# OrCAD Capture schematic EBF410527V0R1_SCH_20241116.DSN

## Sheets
1 01  Content: title: 野火_LubanCat_RV06_IOS_底板原理图; rev: V0R2; note: Content; note: https://yehuosm.tmall.com
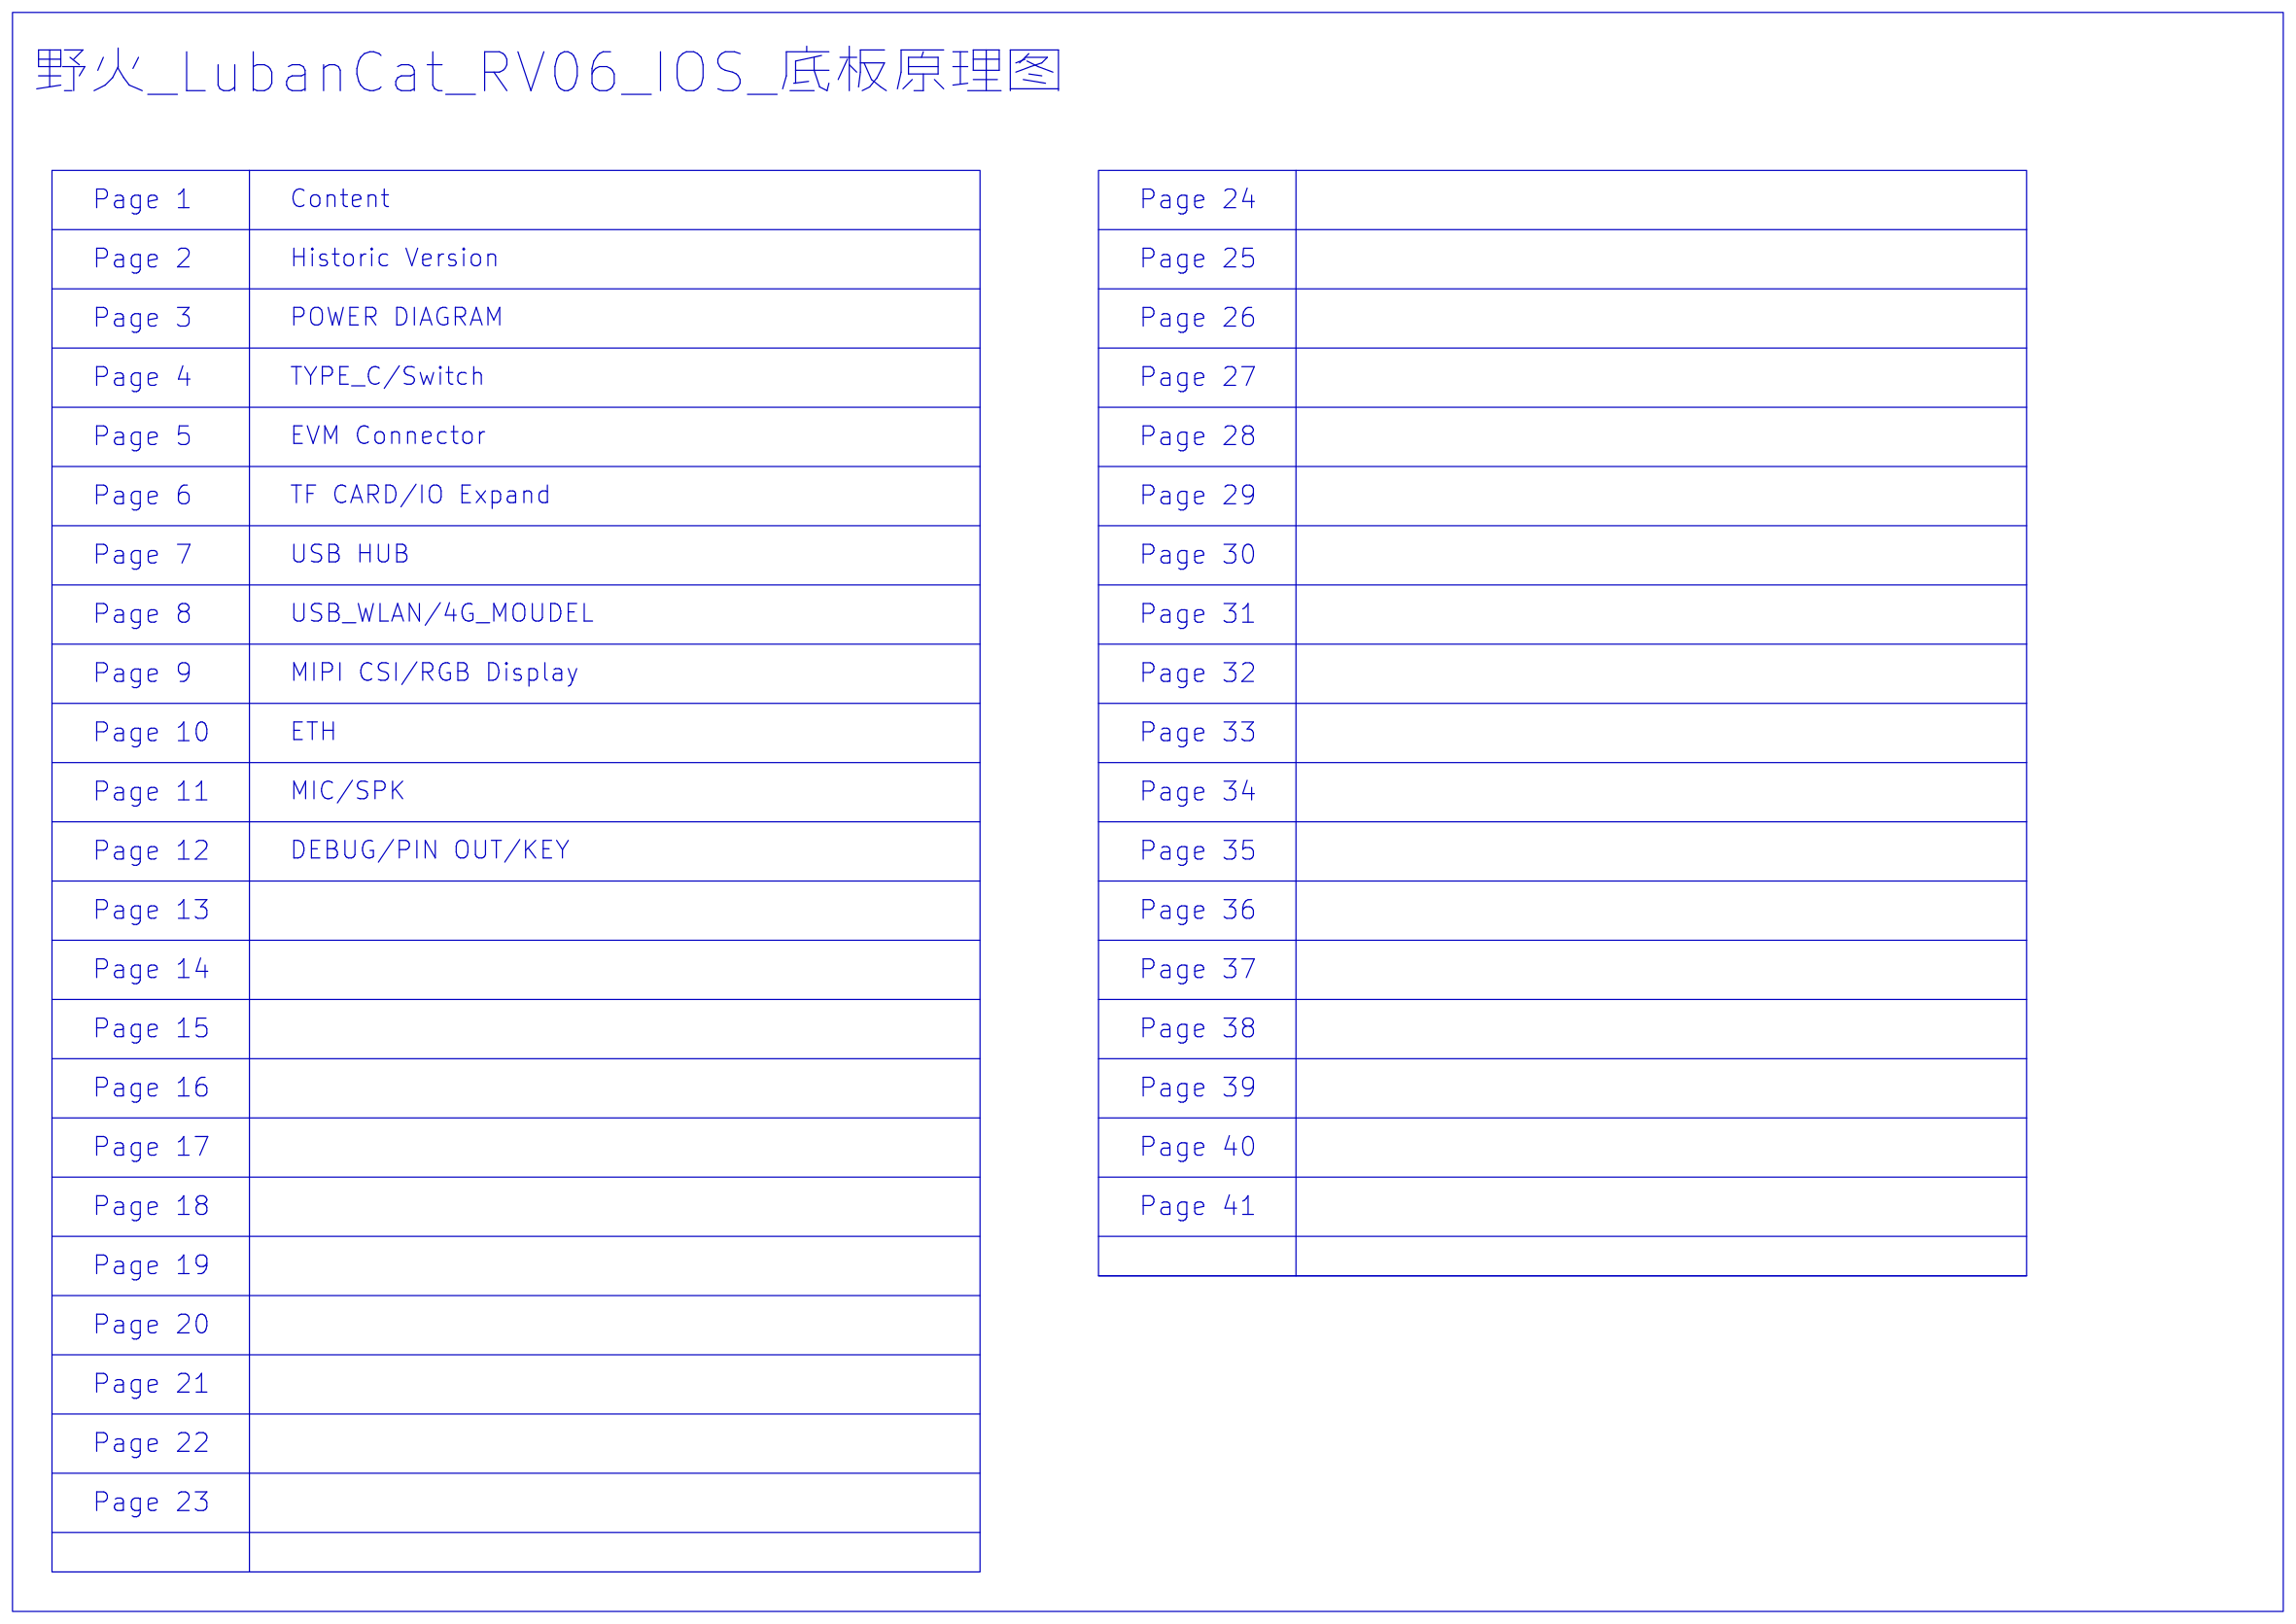
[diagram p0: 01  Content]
2 02 Historic Version: note: Historic Version
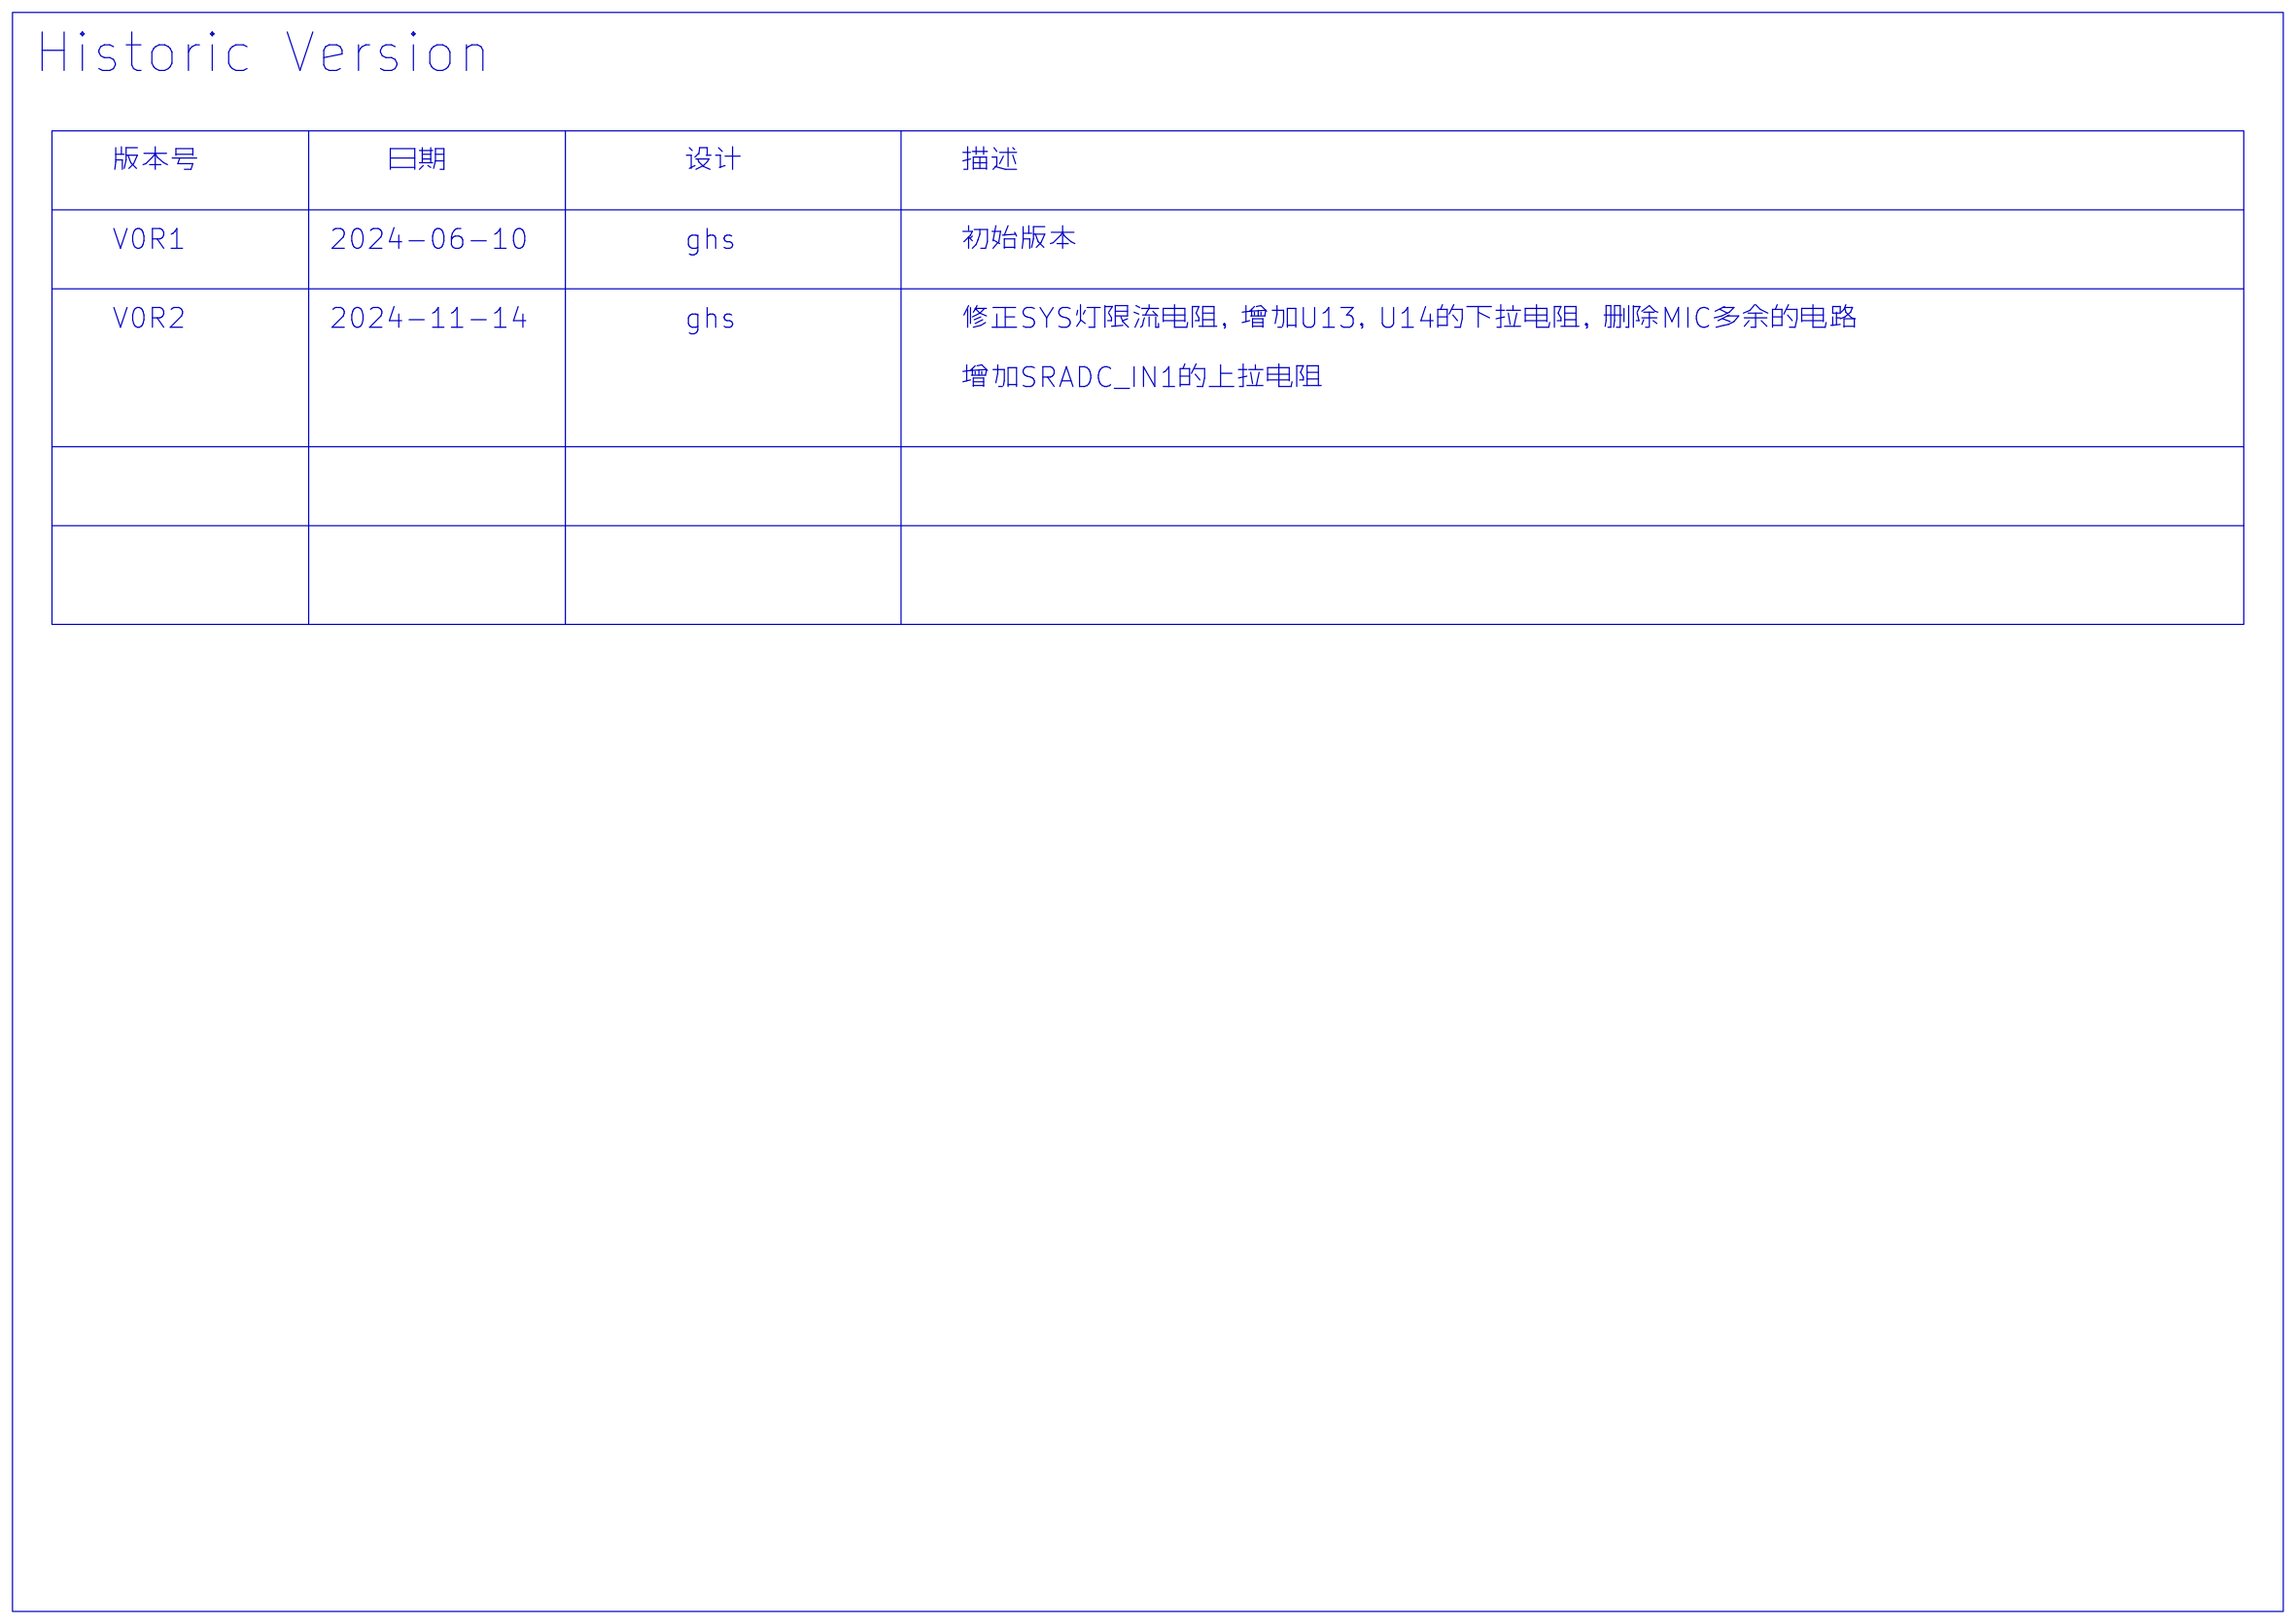
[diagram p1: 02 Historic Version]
3 03 POWER DIAGRAM: note: POWER DIAGRAM
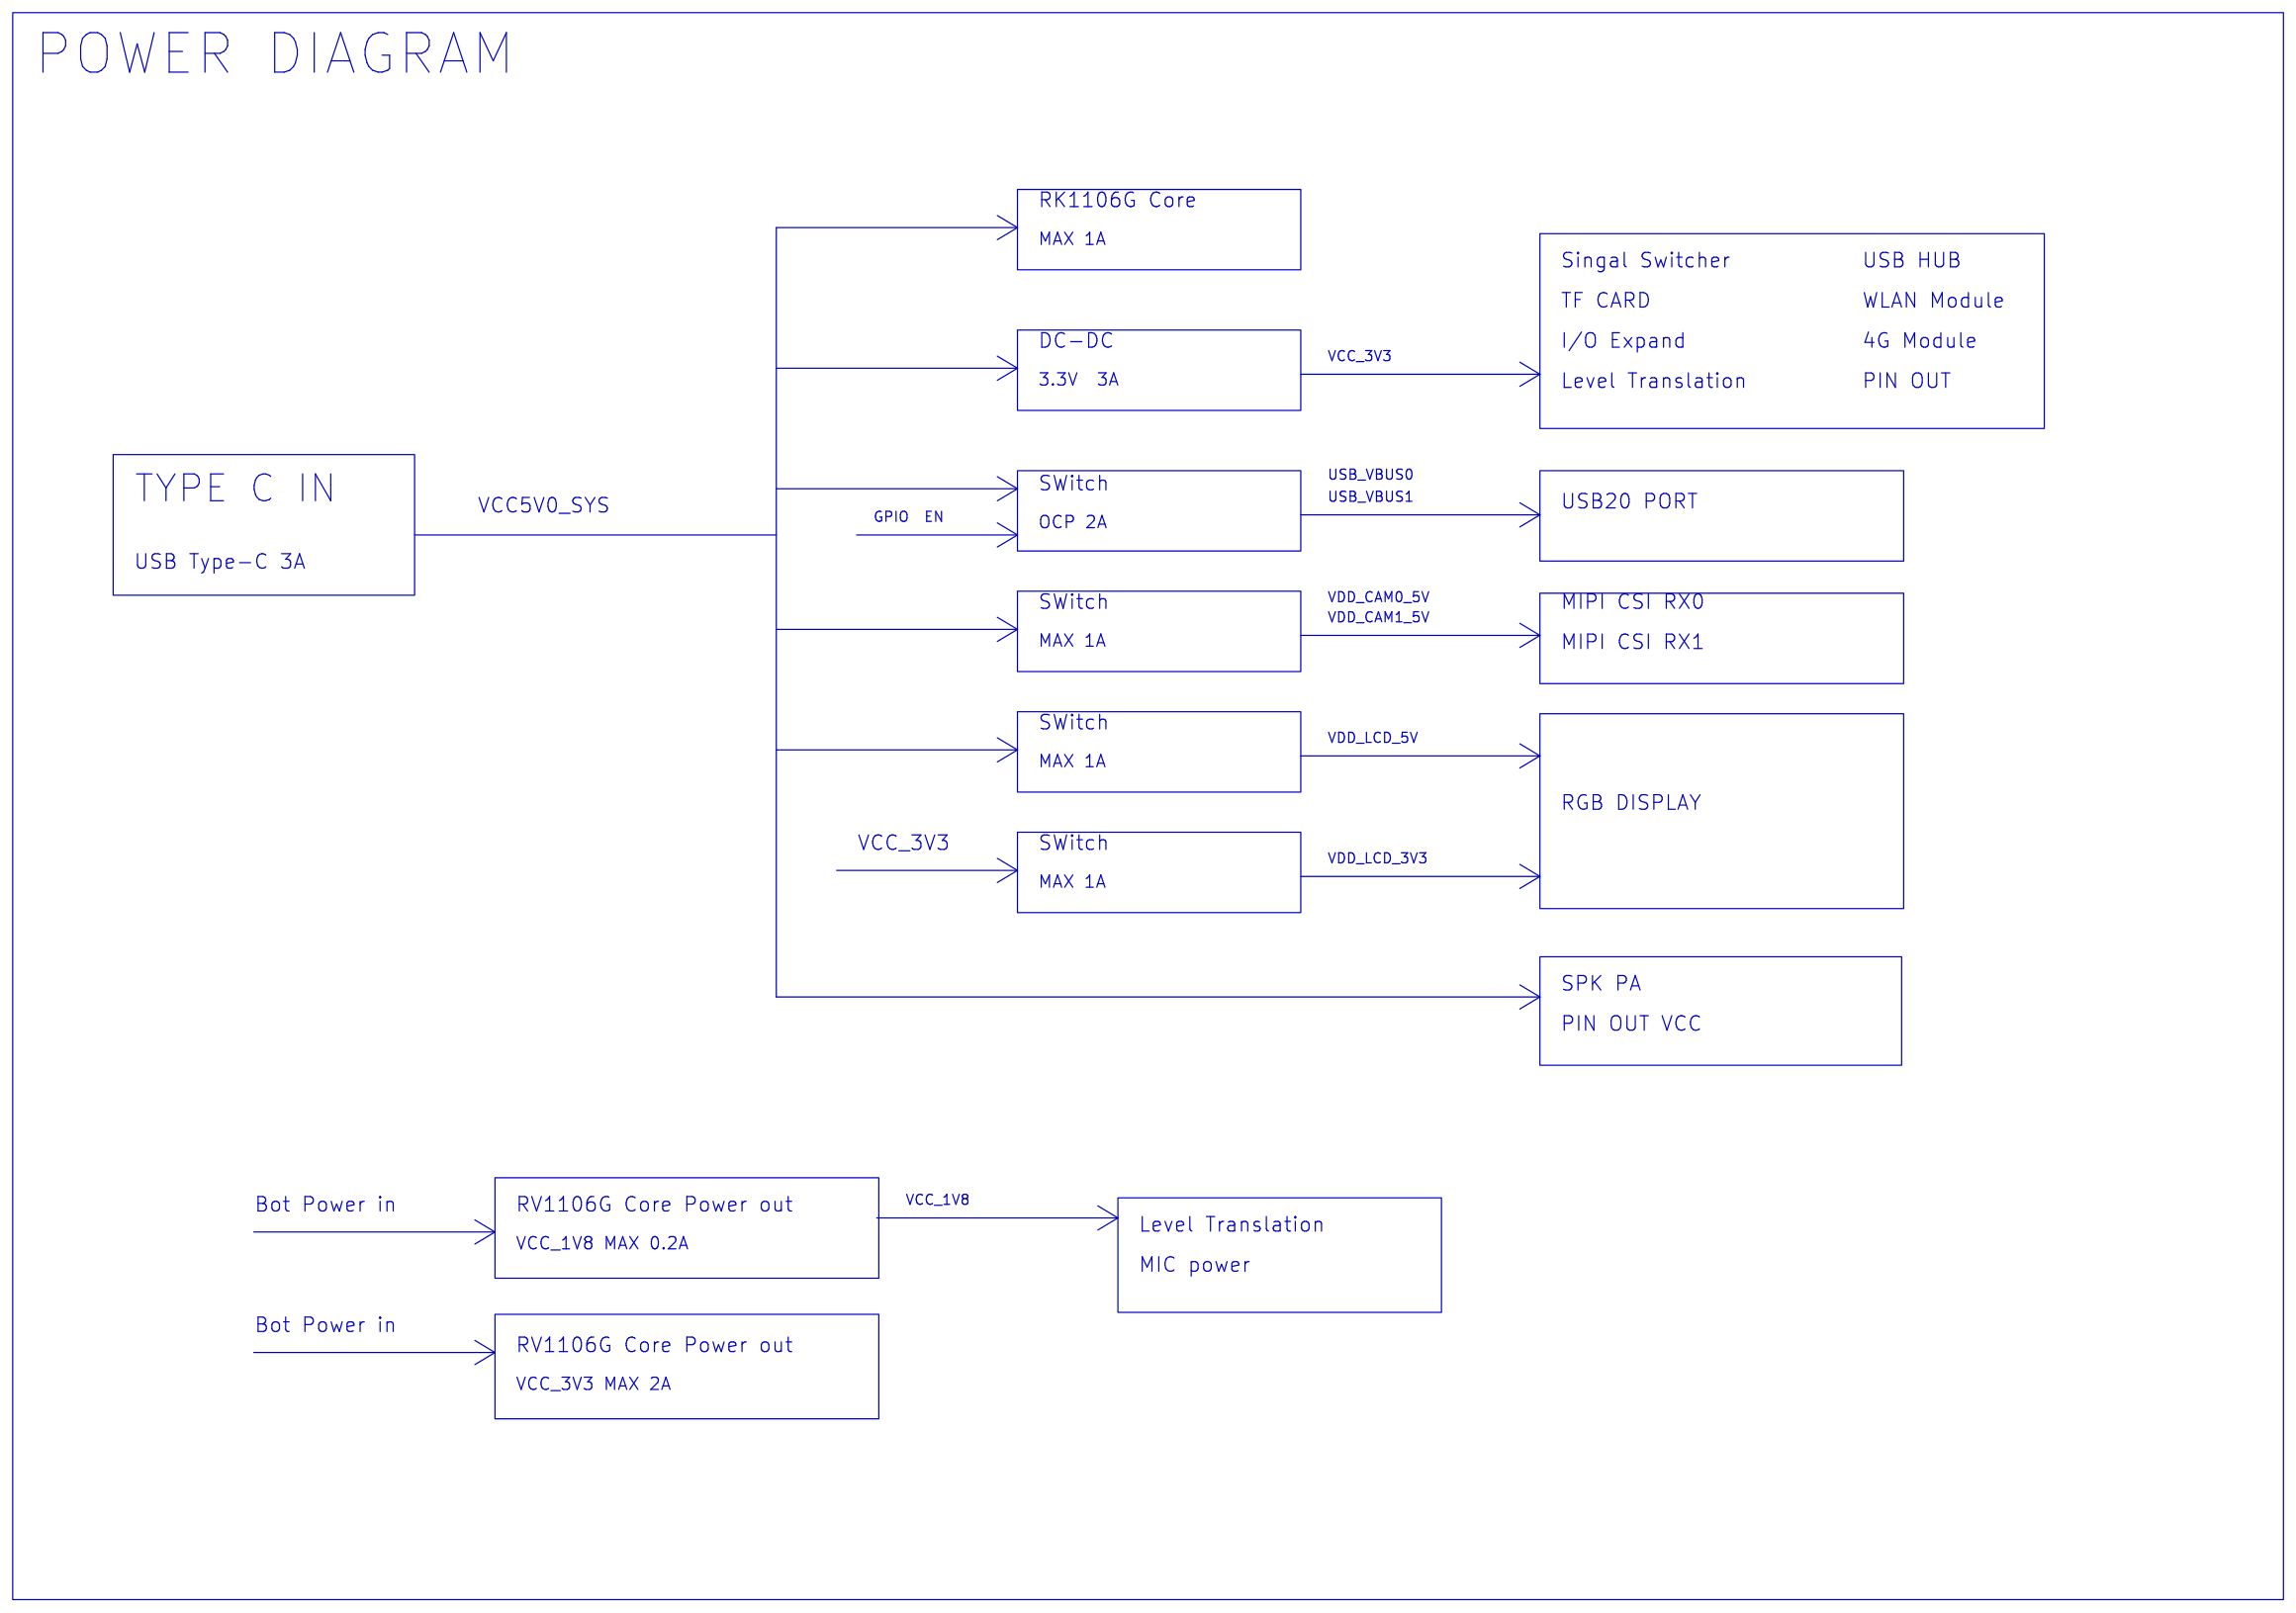
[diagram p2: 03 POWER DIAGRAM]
4 05 EVM Connector: size A3; note: EVM Connector
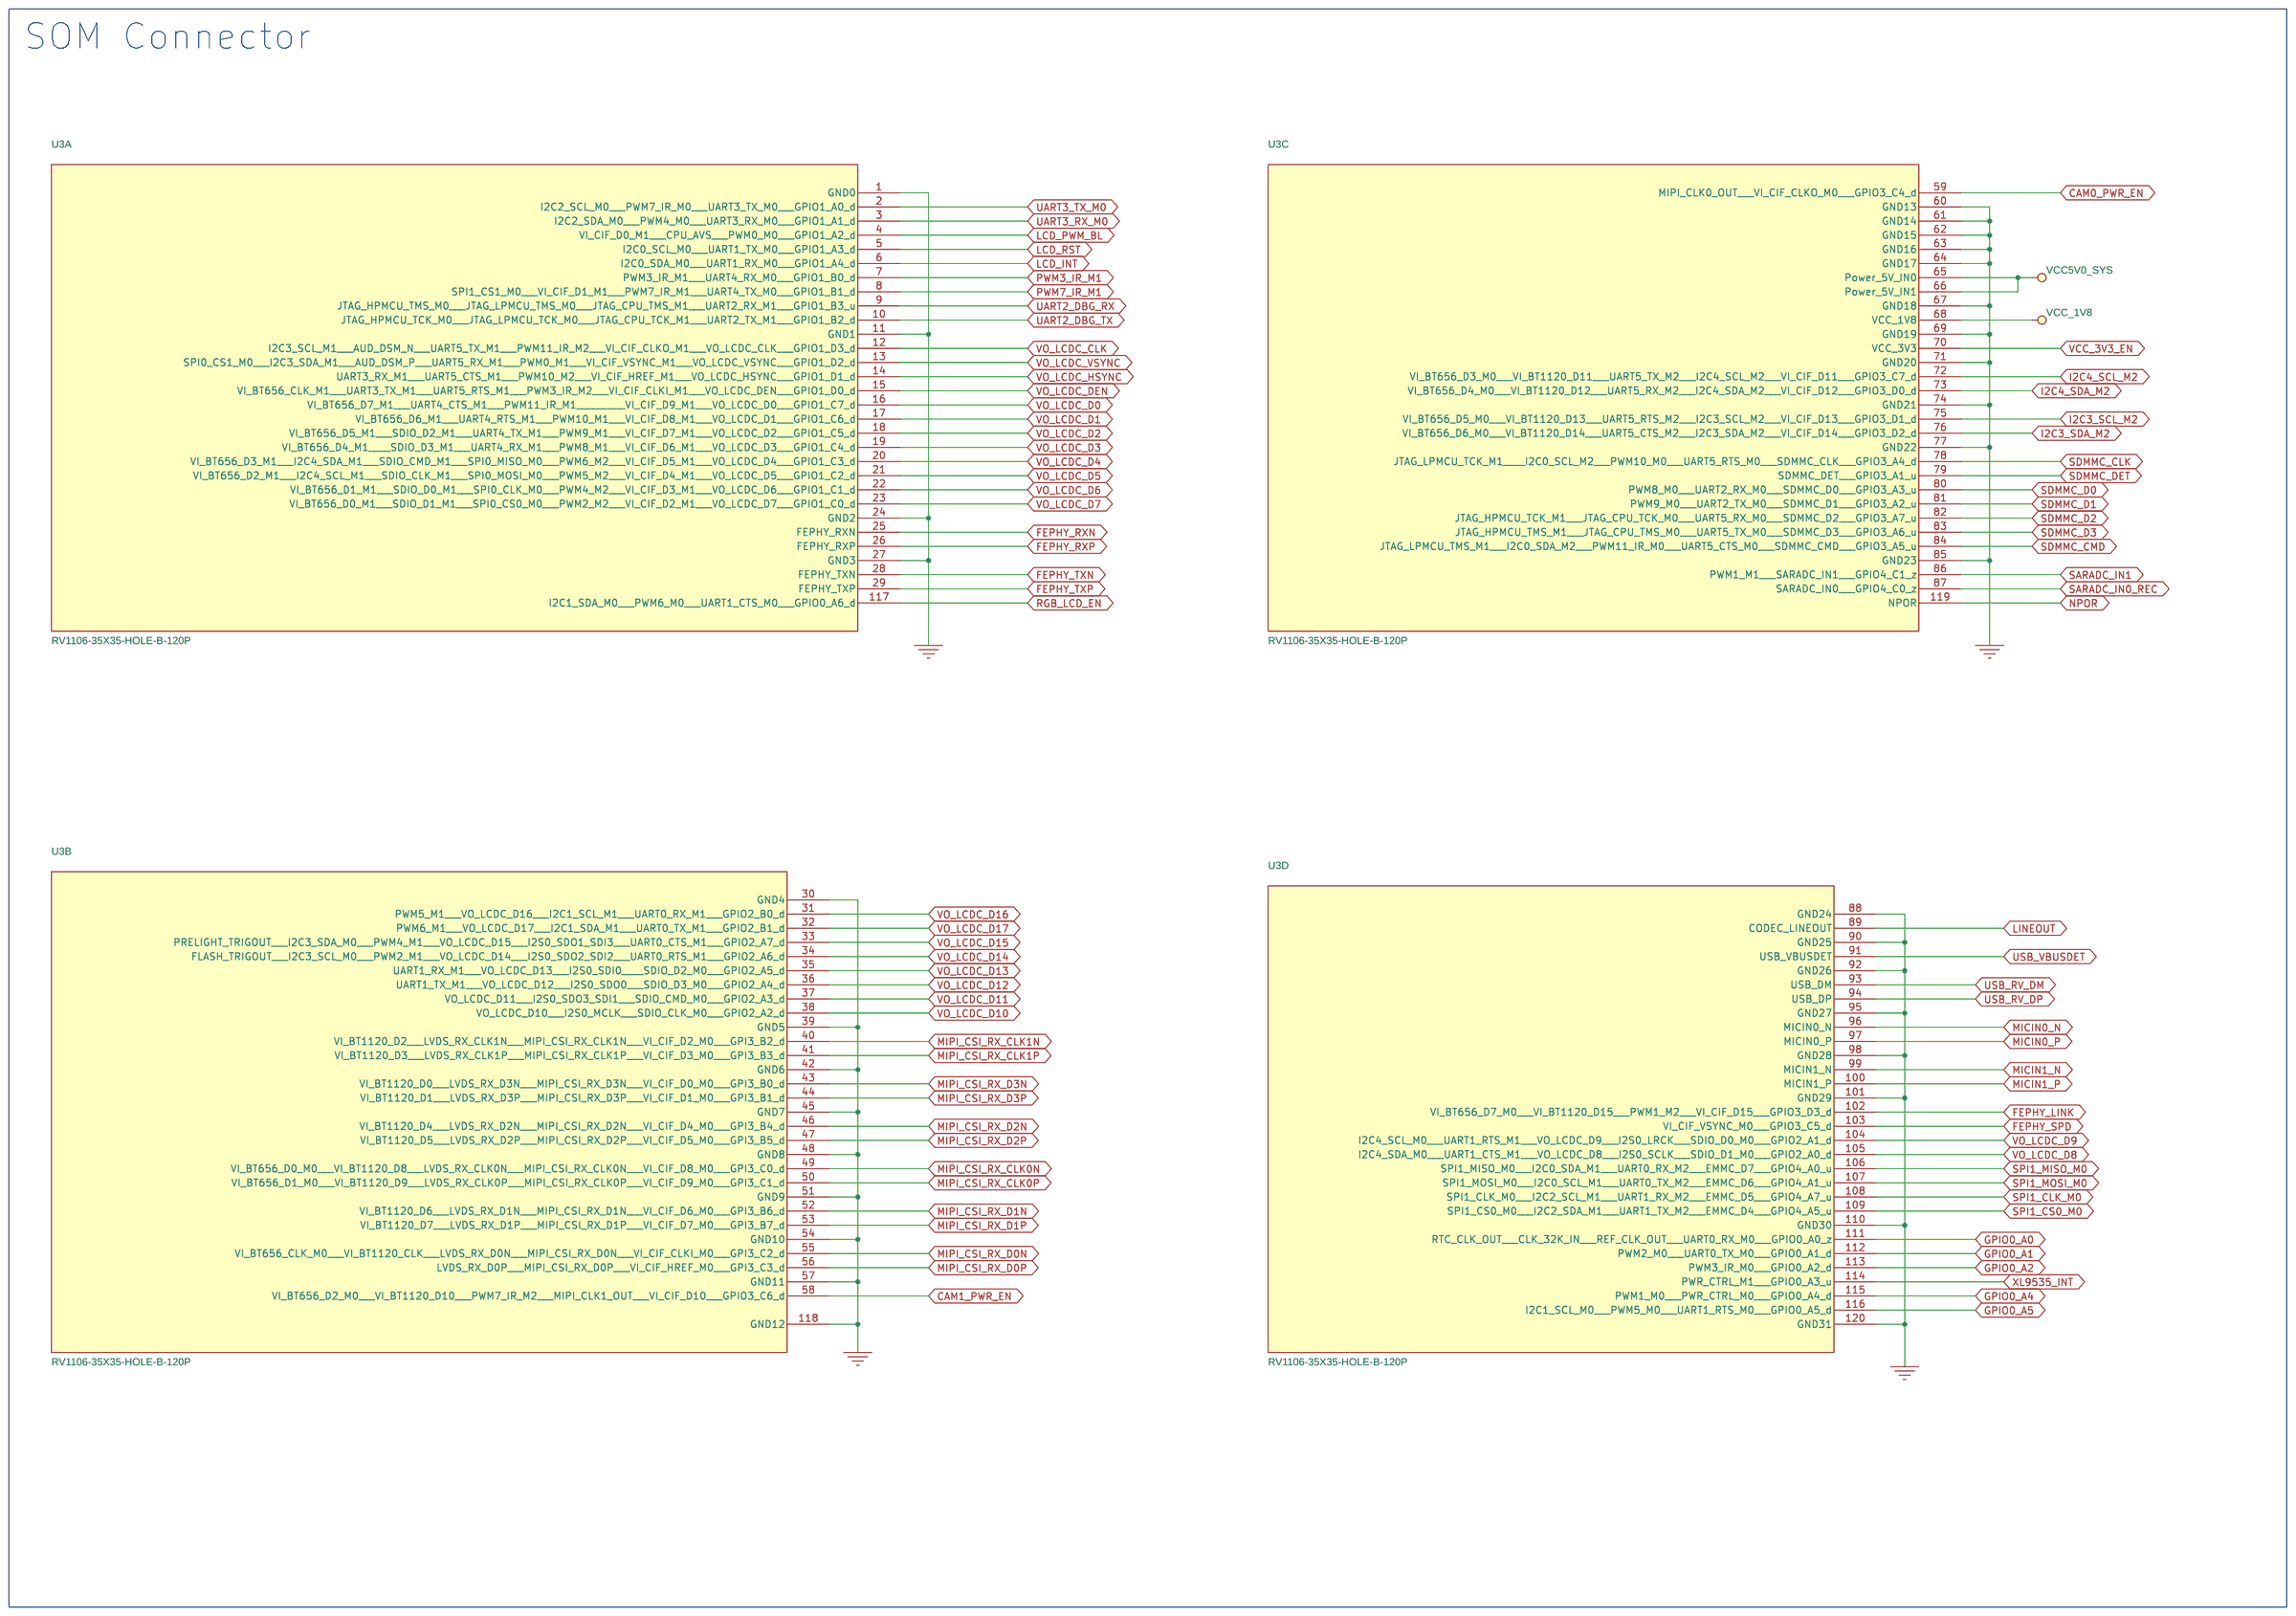
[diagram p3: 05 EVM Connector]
5 07 USB HUB: size A4; note: USB HUB
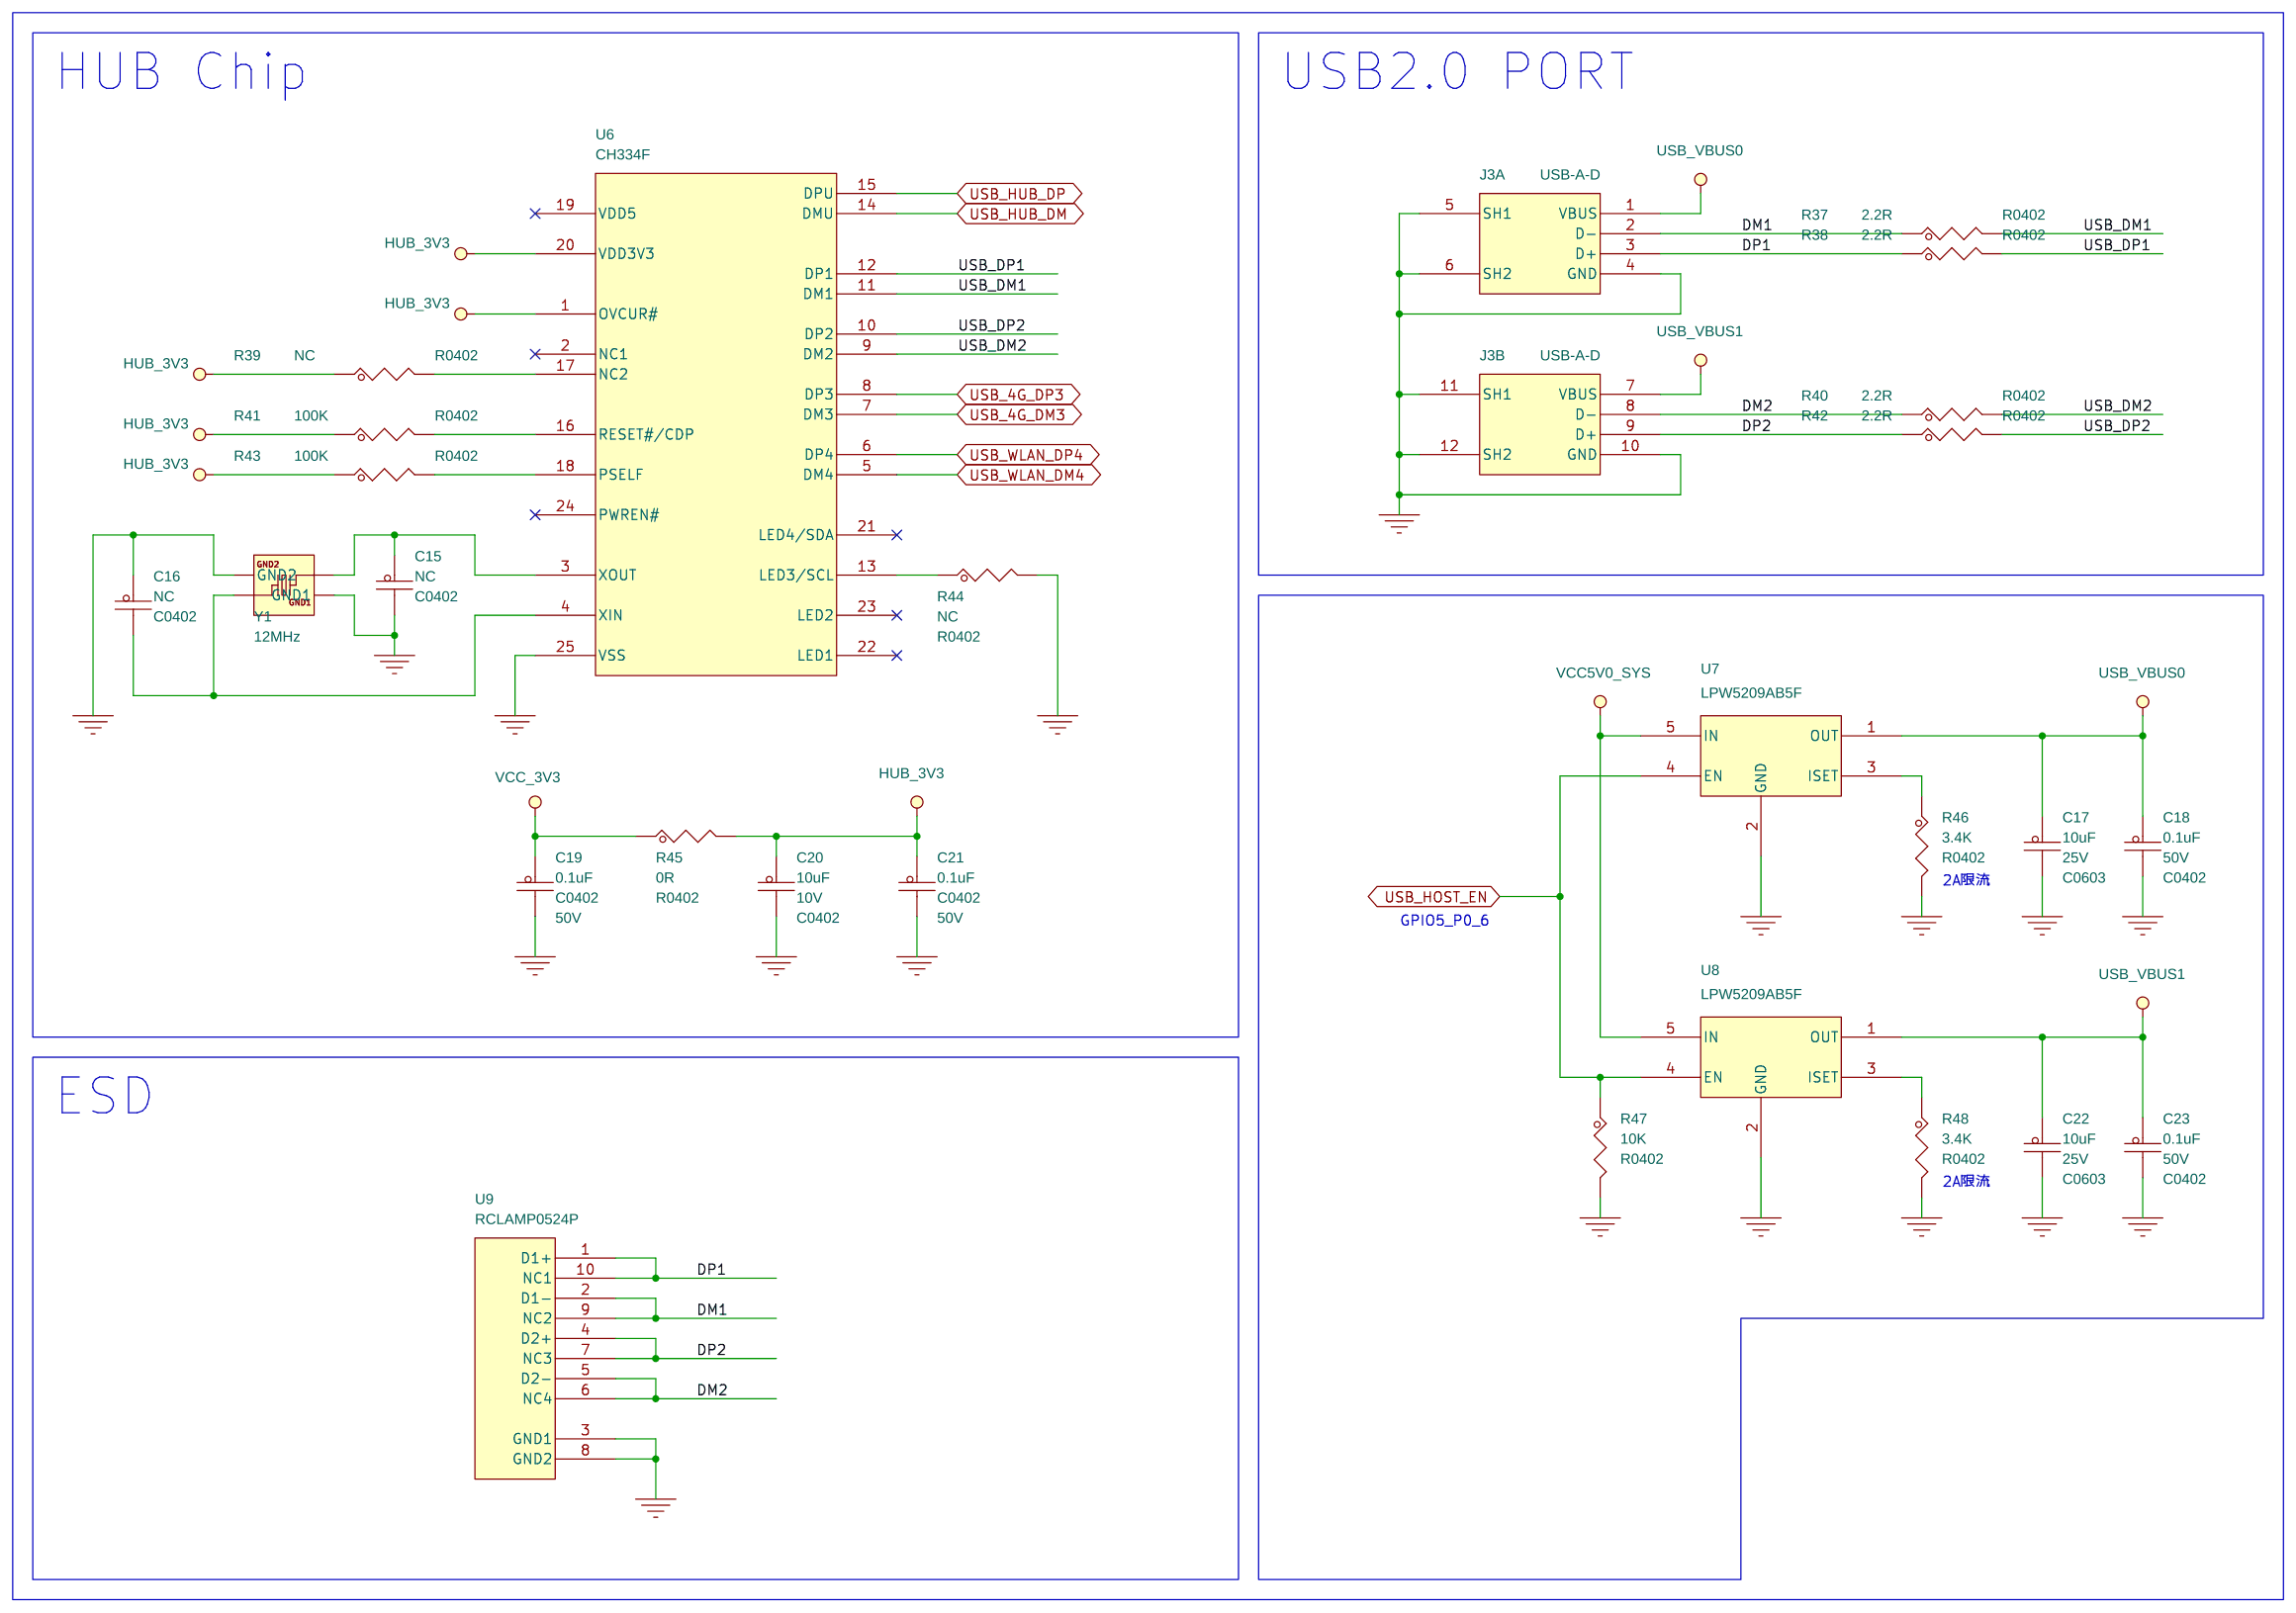
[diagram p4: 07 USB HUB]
6 10 ETH: size A4; note: ETH
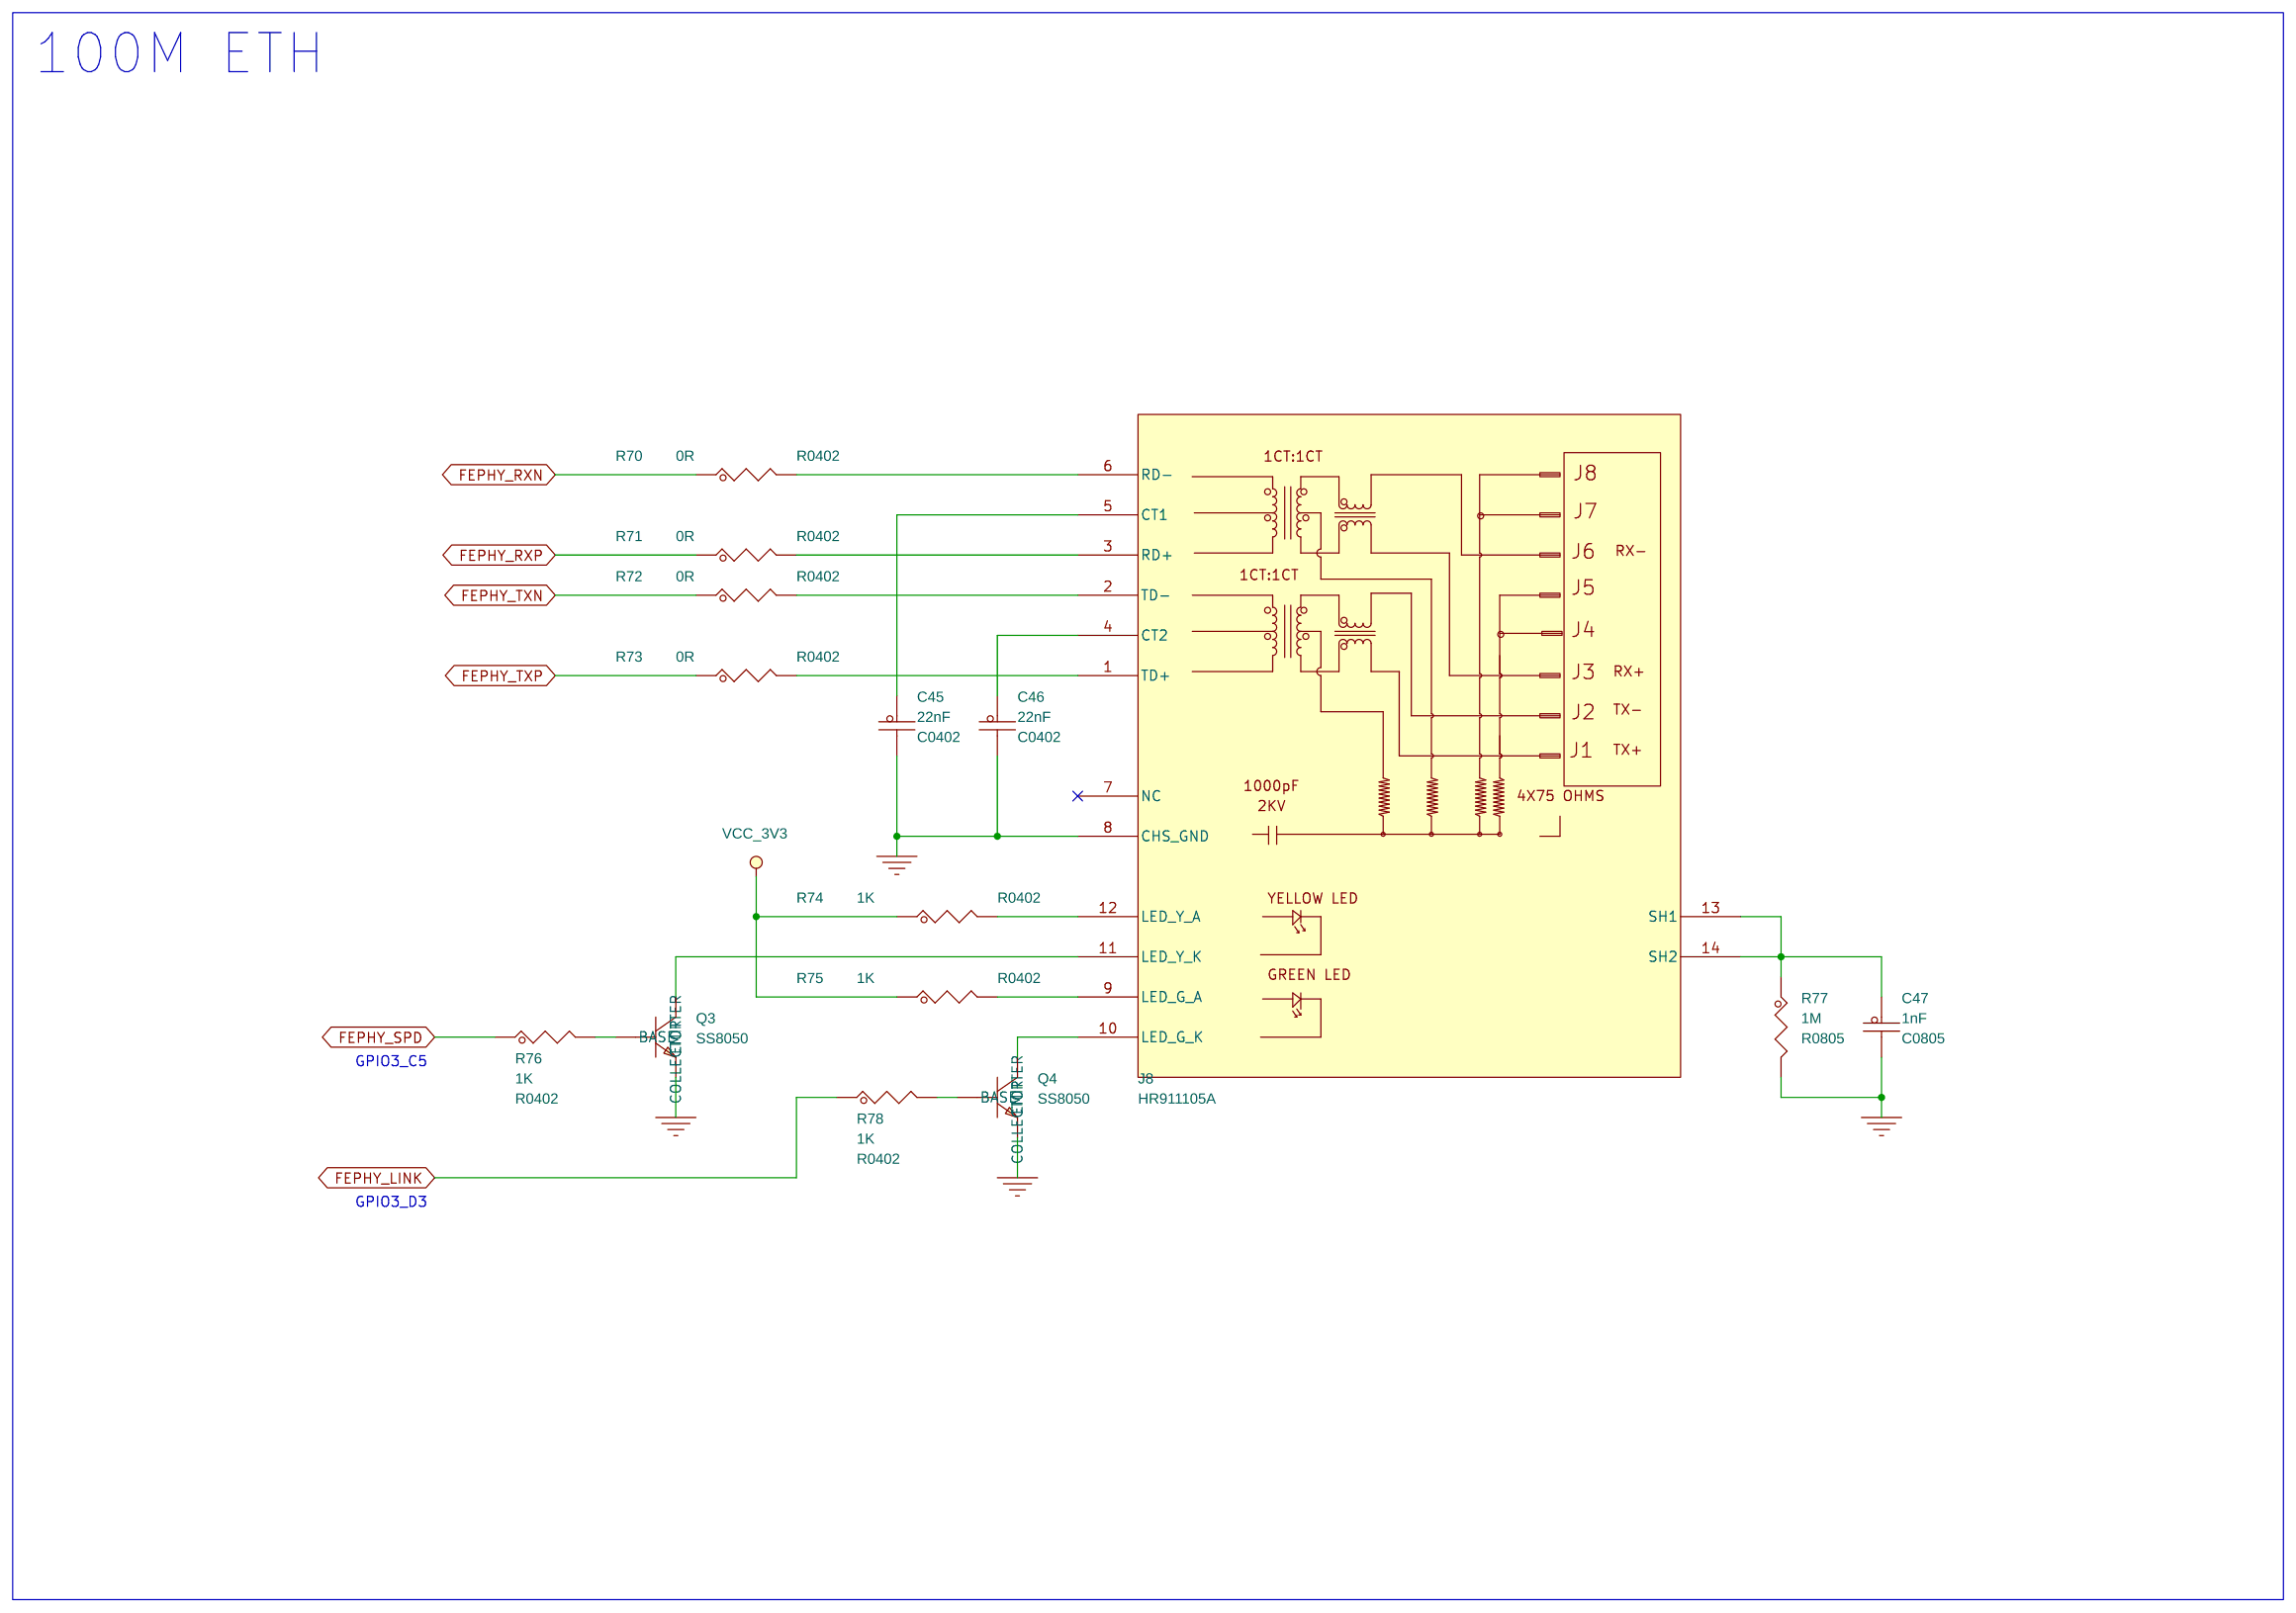
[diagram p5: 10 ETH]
7 11 MIC/SPK: size A4; note: MIC/SPK
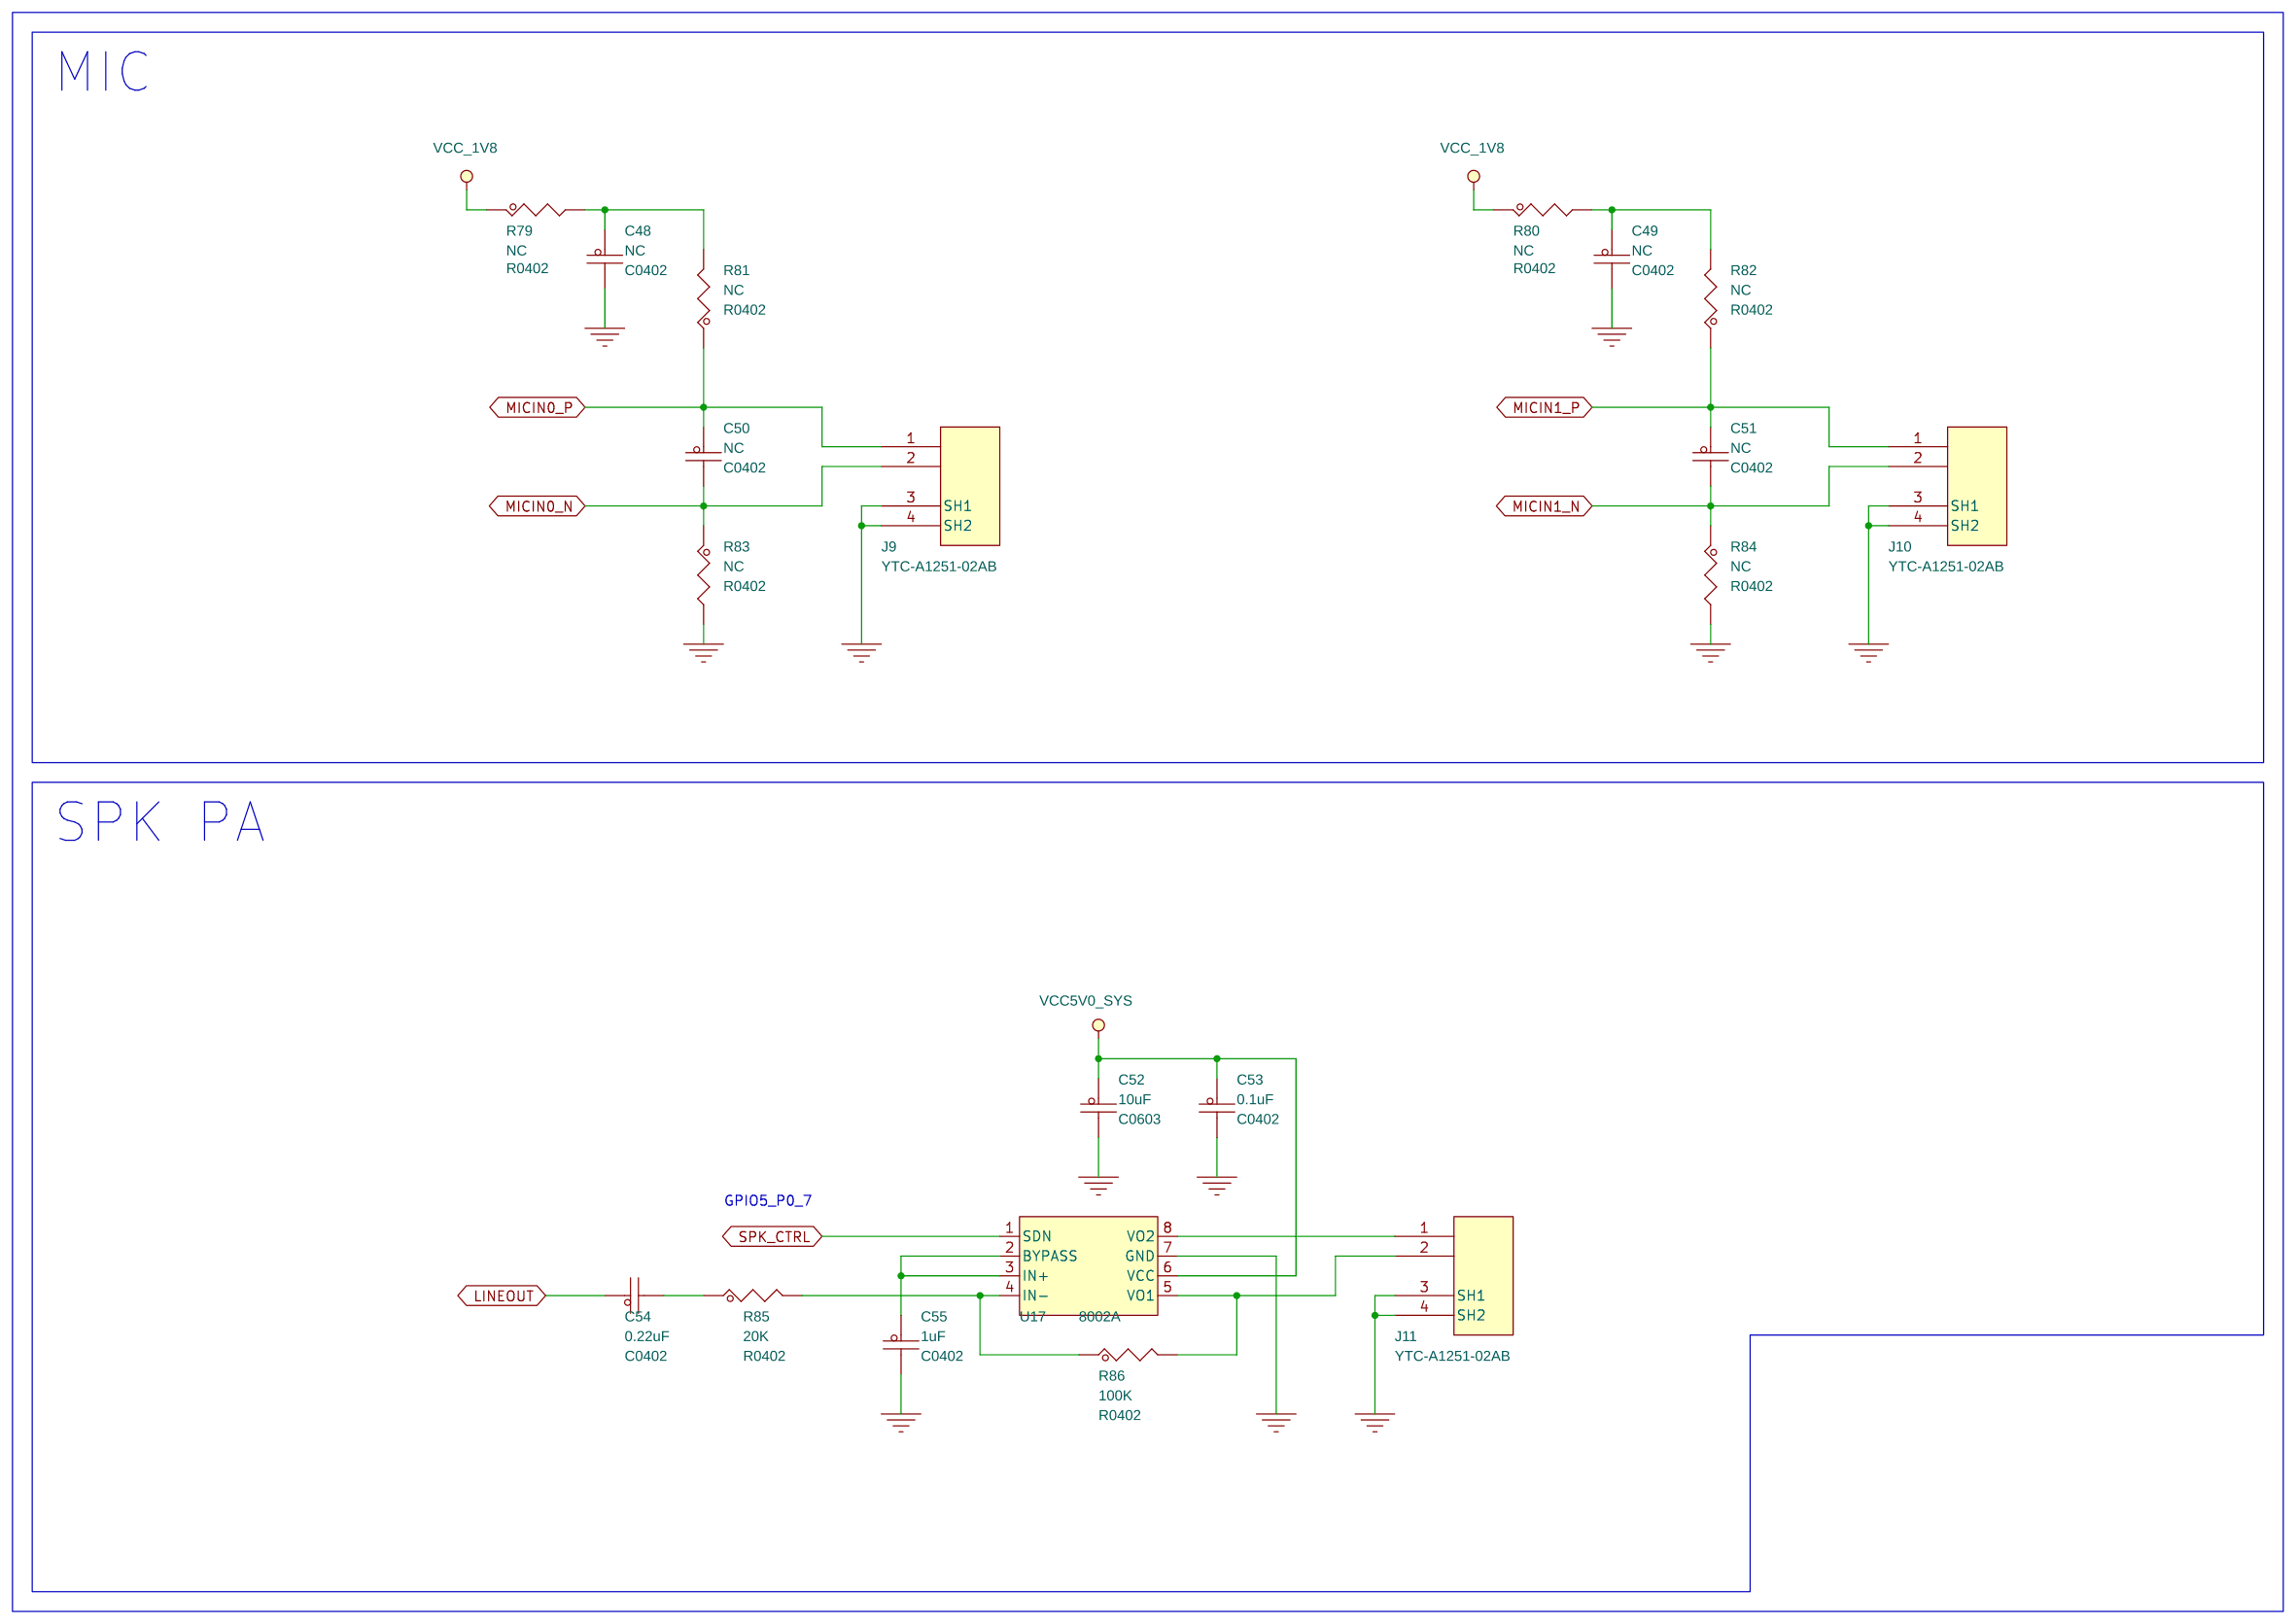
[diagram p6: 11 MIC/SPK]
8 04 TYPE_C/Switch: size A4; note: TYPE_C/Switch
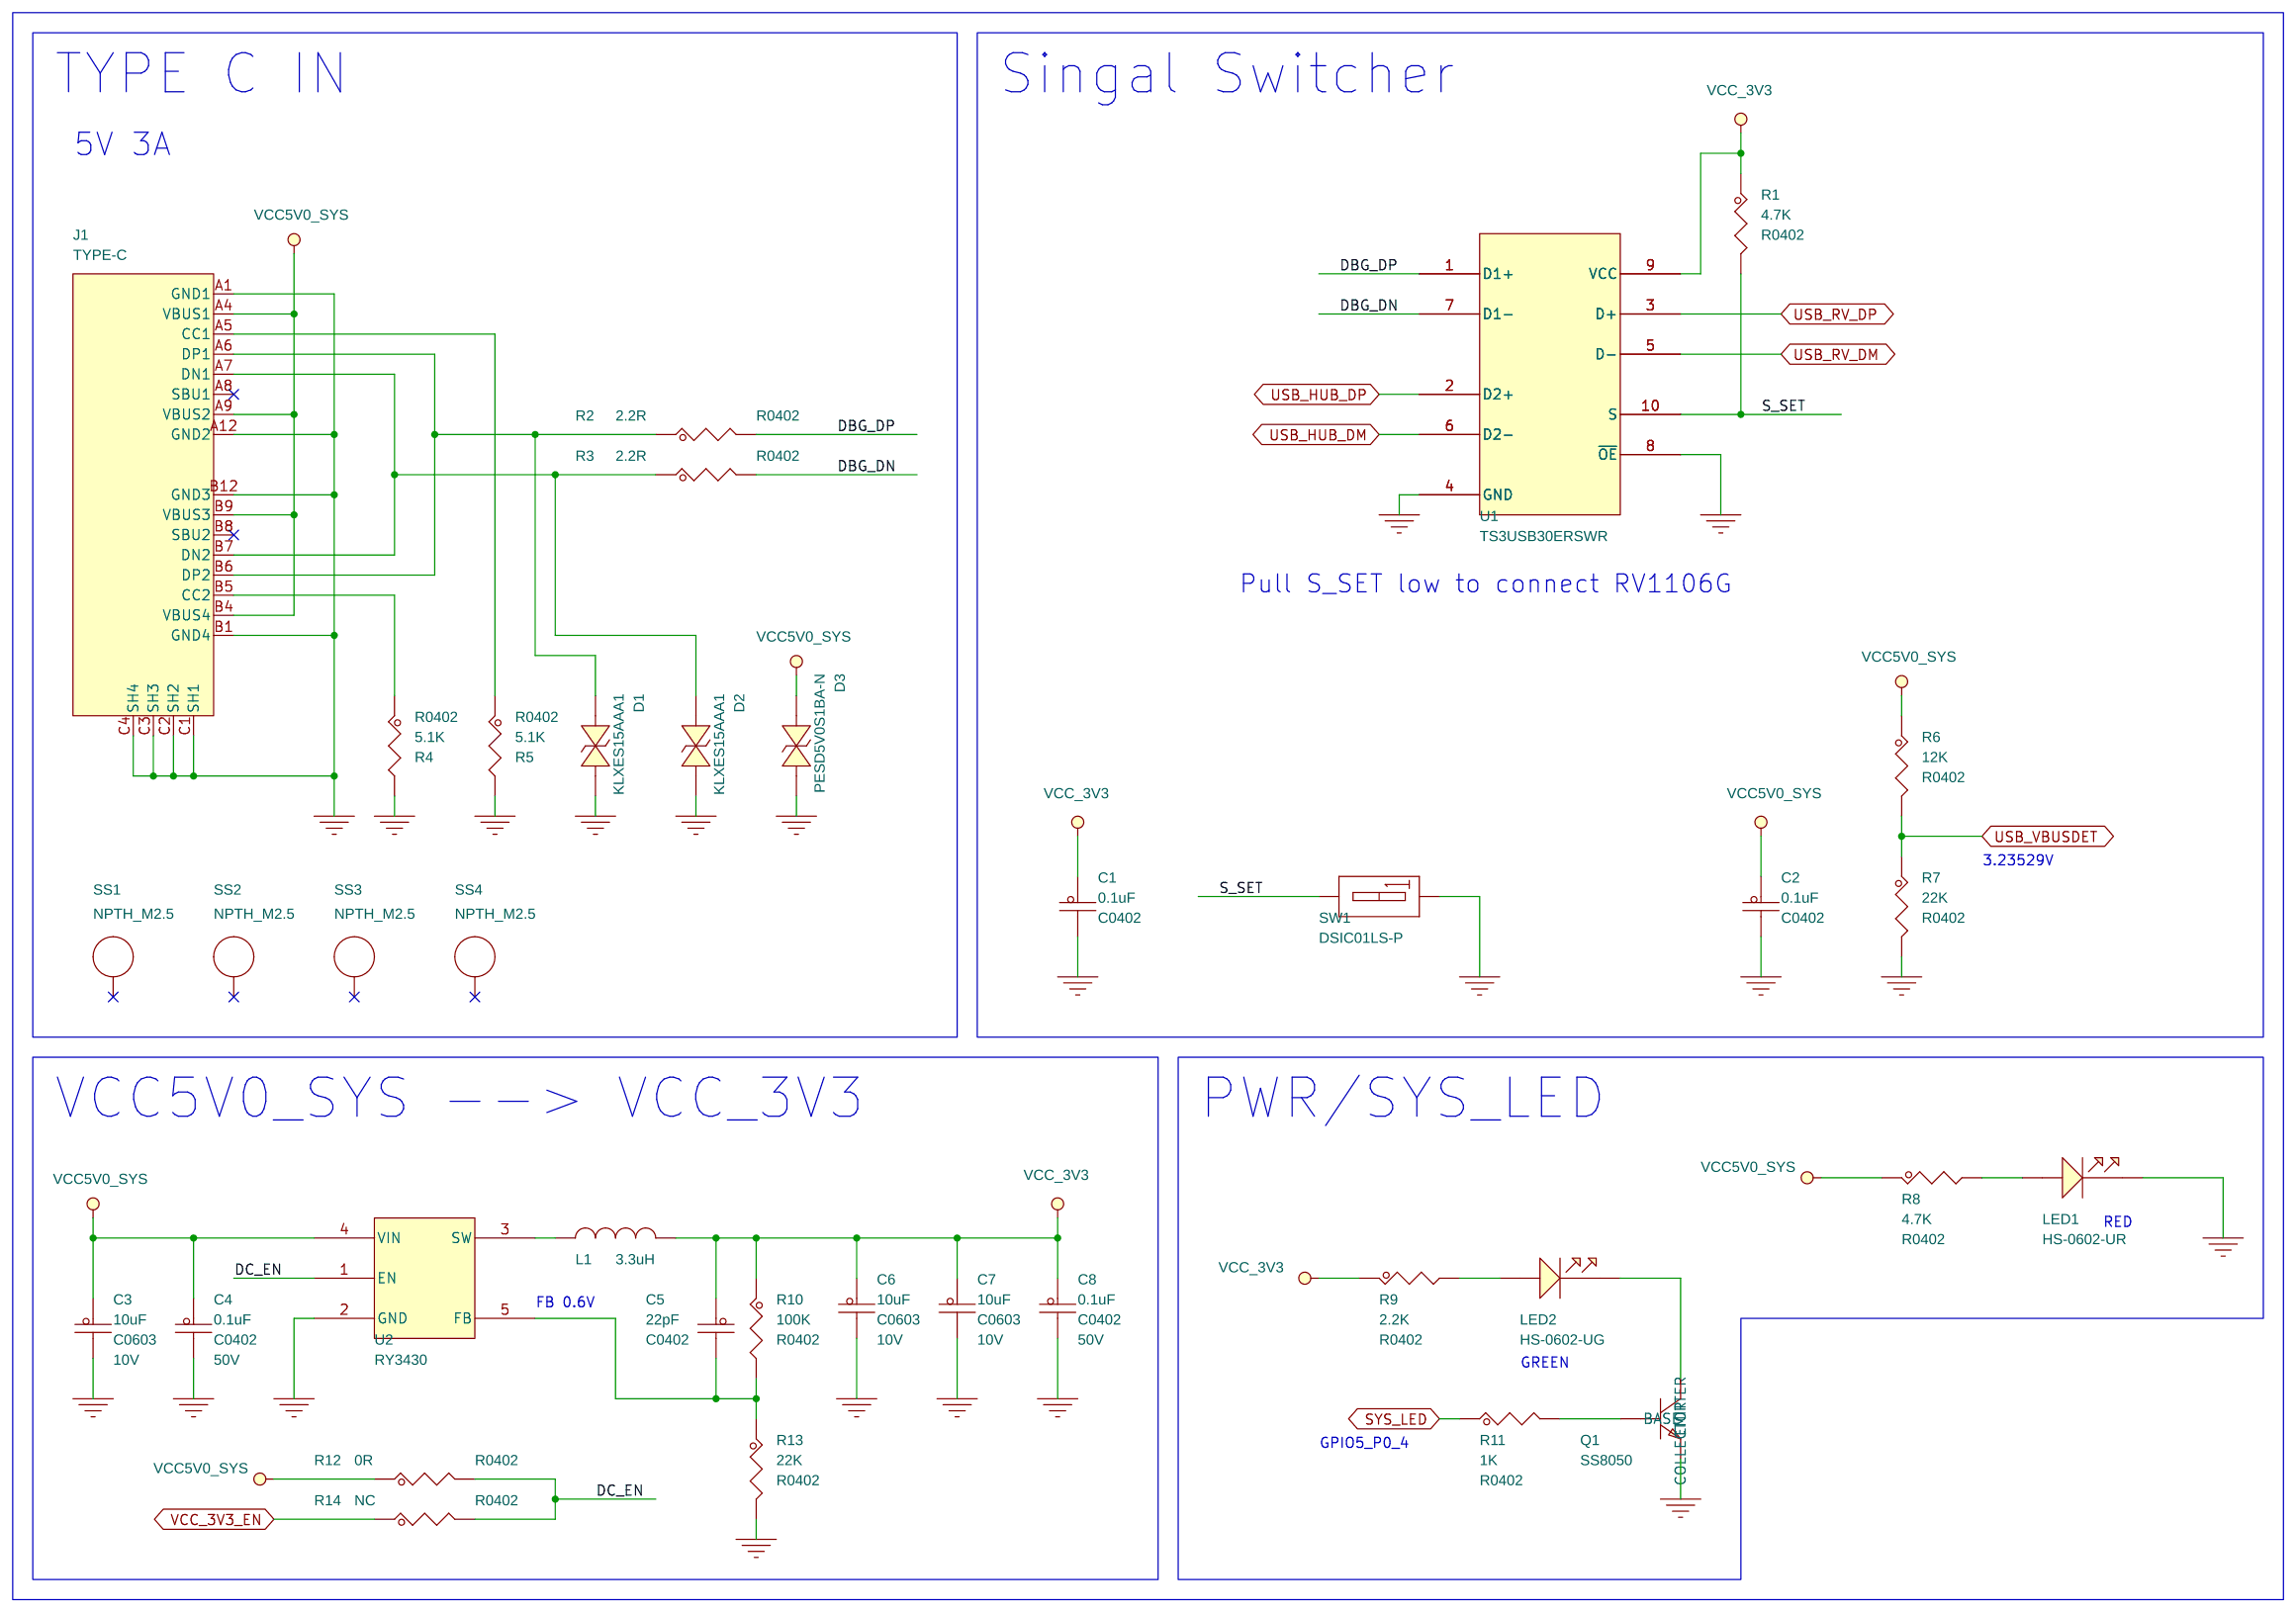
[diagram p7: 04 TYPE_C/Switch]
9 12 DEBUG/PIN OUT/KEY: size A4; note: DEBUG/PIN OUT/KEY
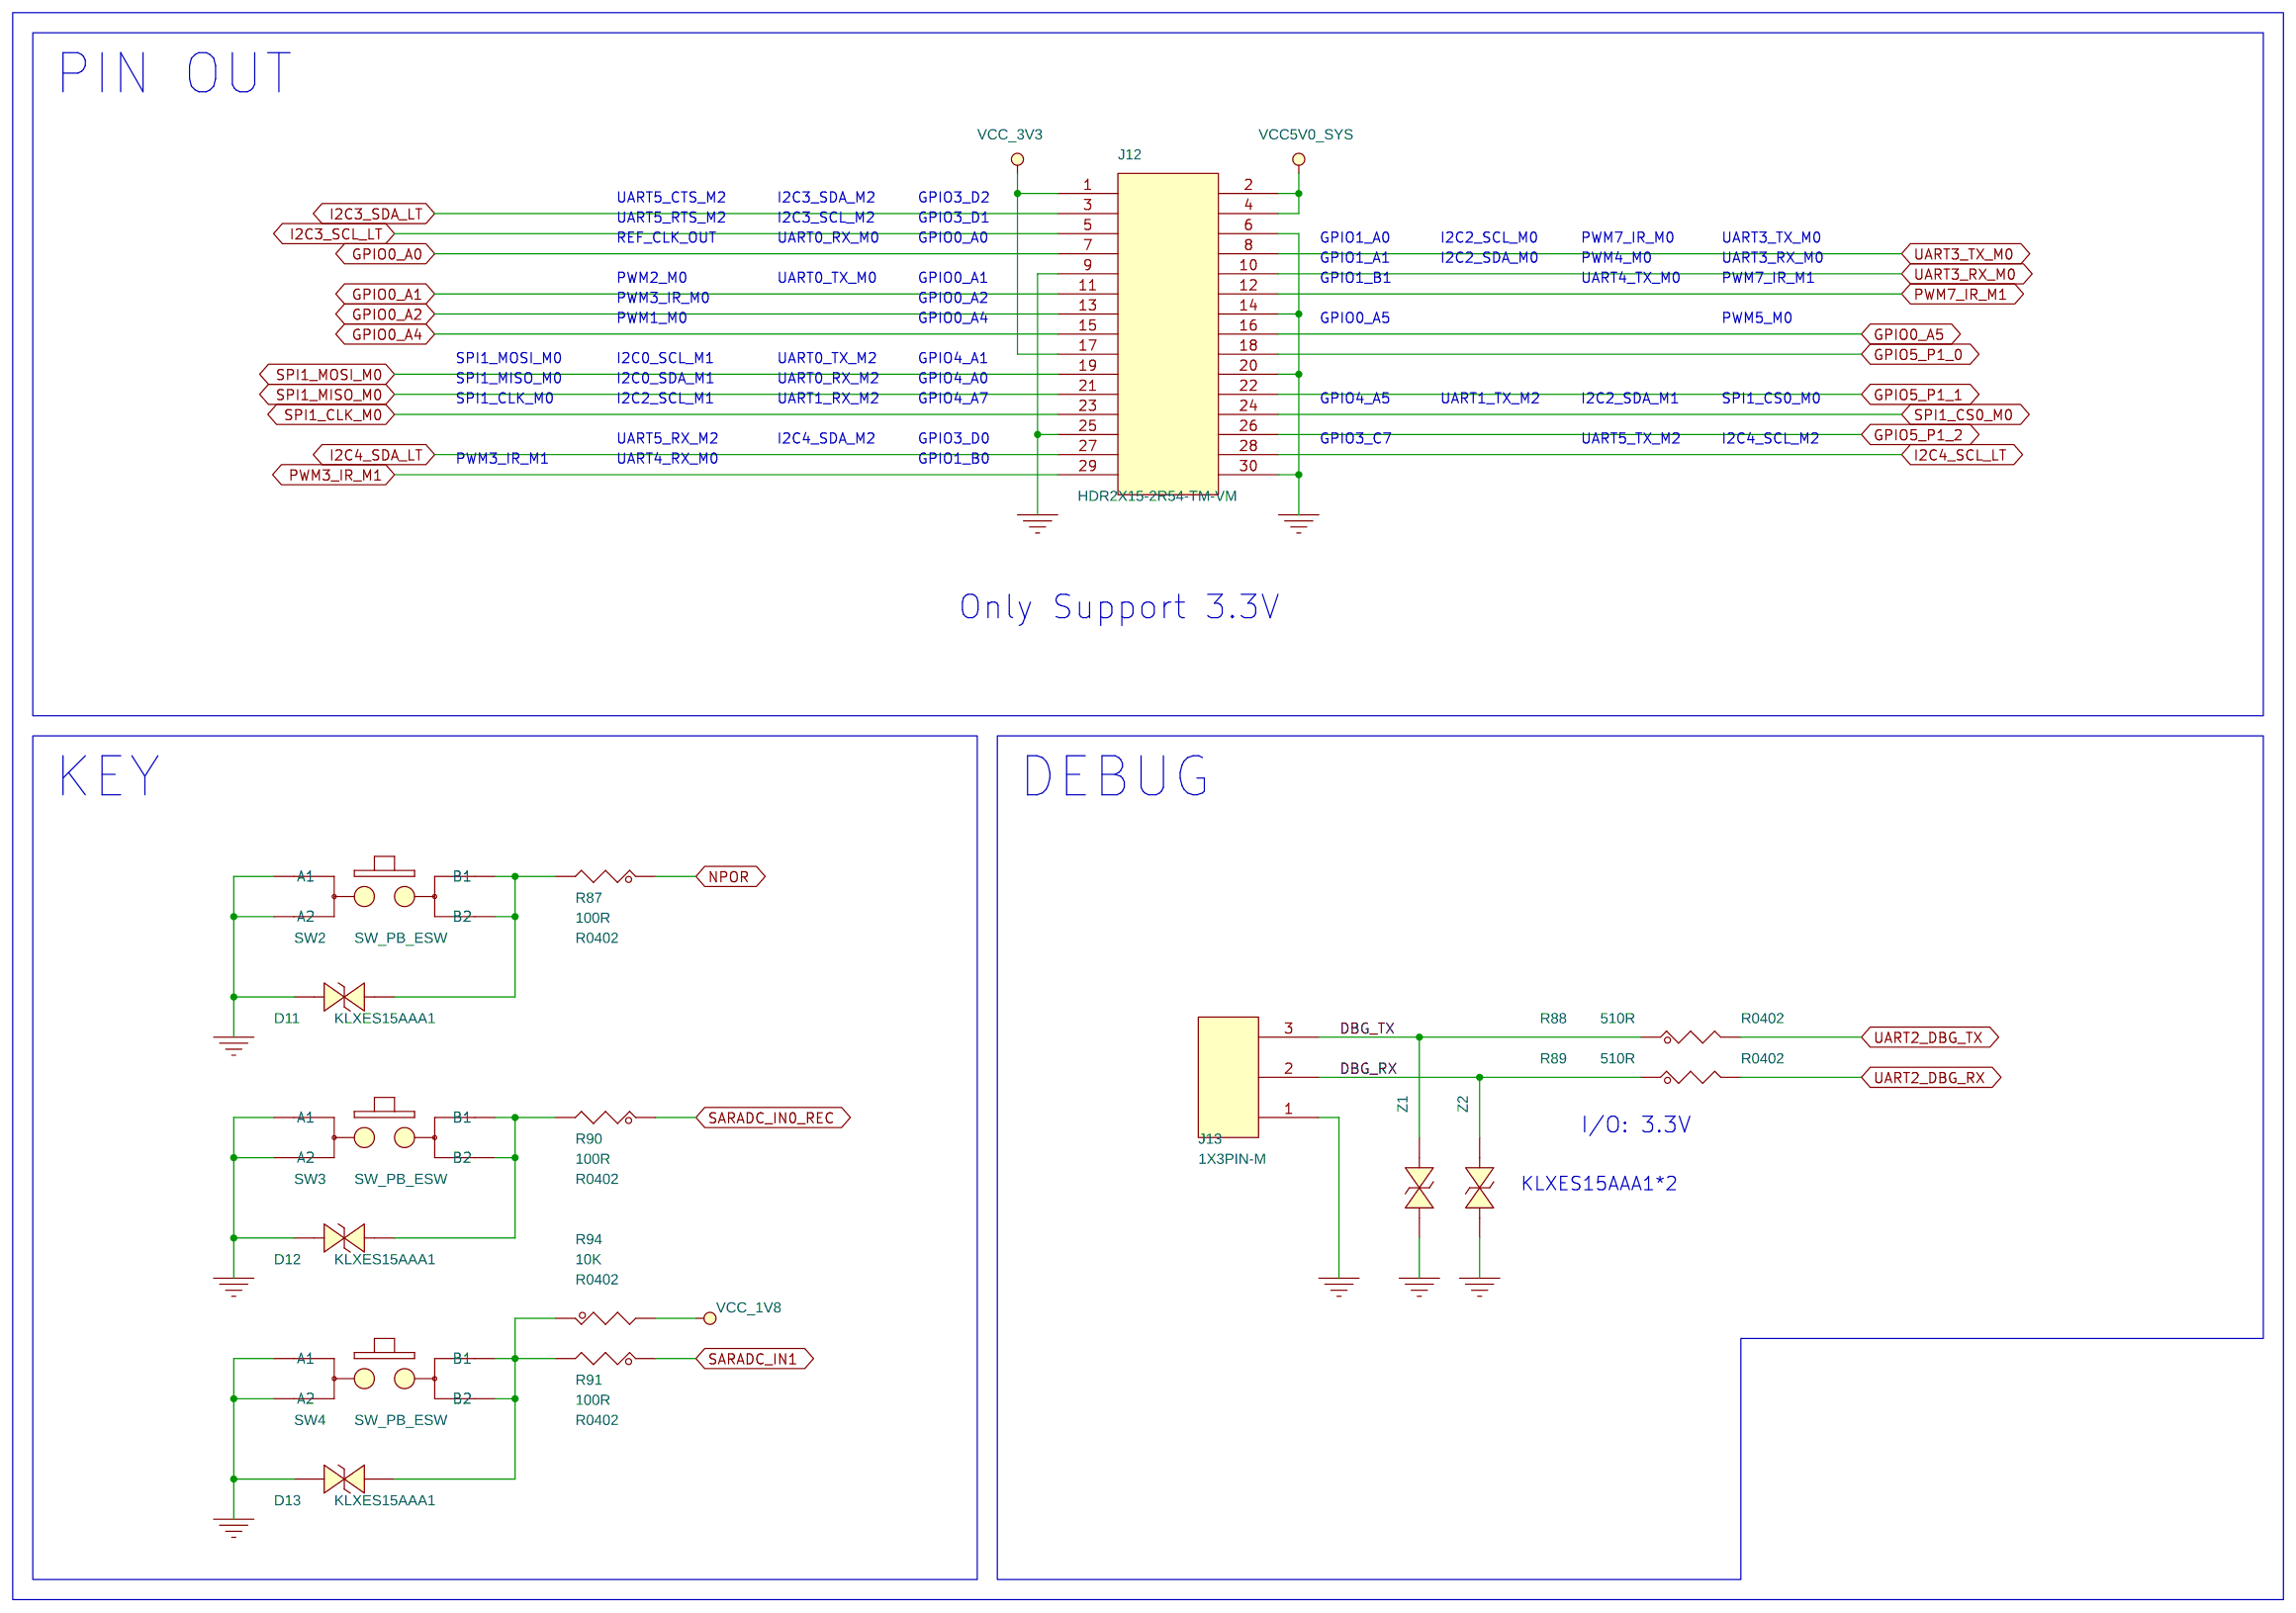
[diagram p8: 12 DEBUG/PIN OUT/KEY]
10 06 TF CARD/IO Expand: size A3; note: TF CARD/IO Expand
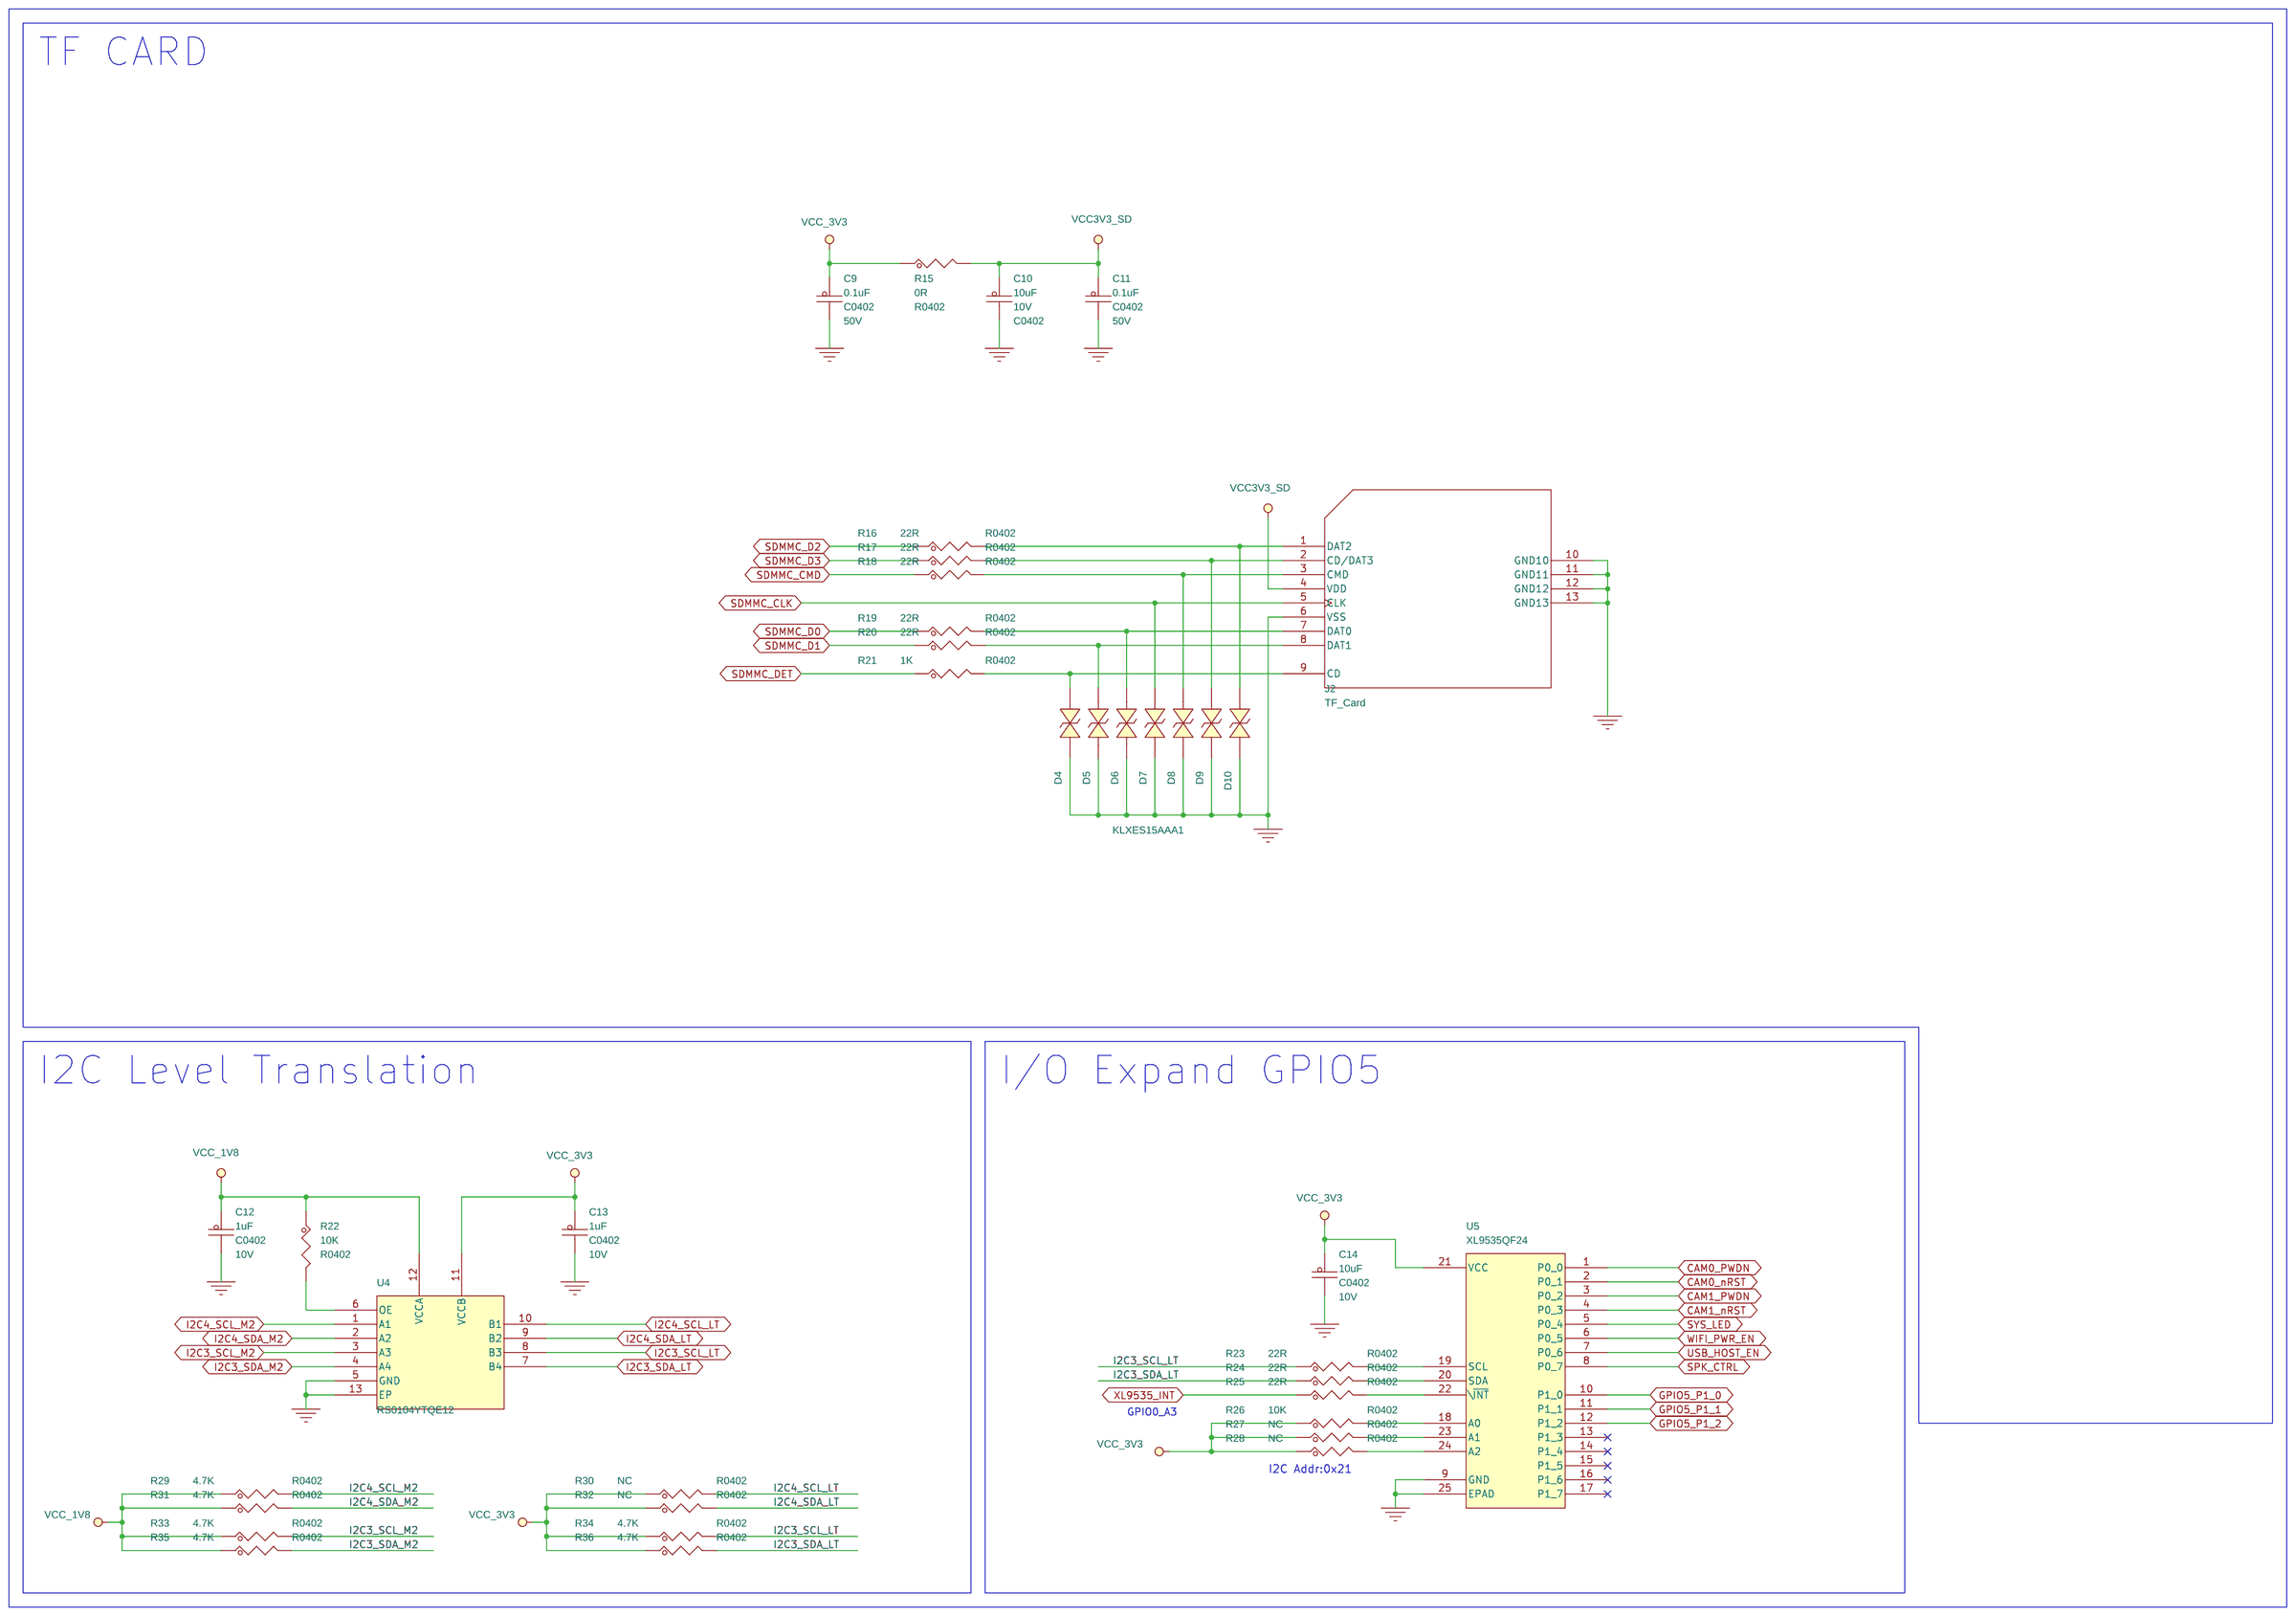
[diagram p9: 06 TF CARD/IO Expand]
11 08 USB_WLAN/4G_MOUDEL: size A4; note: USB_WLAN/4G_MOUDEL
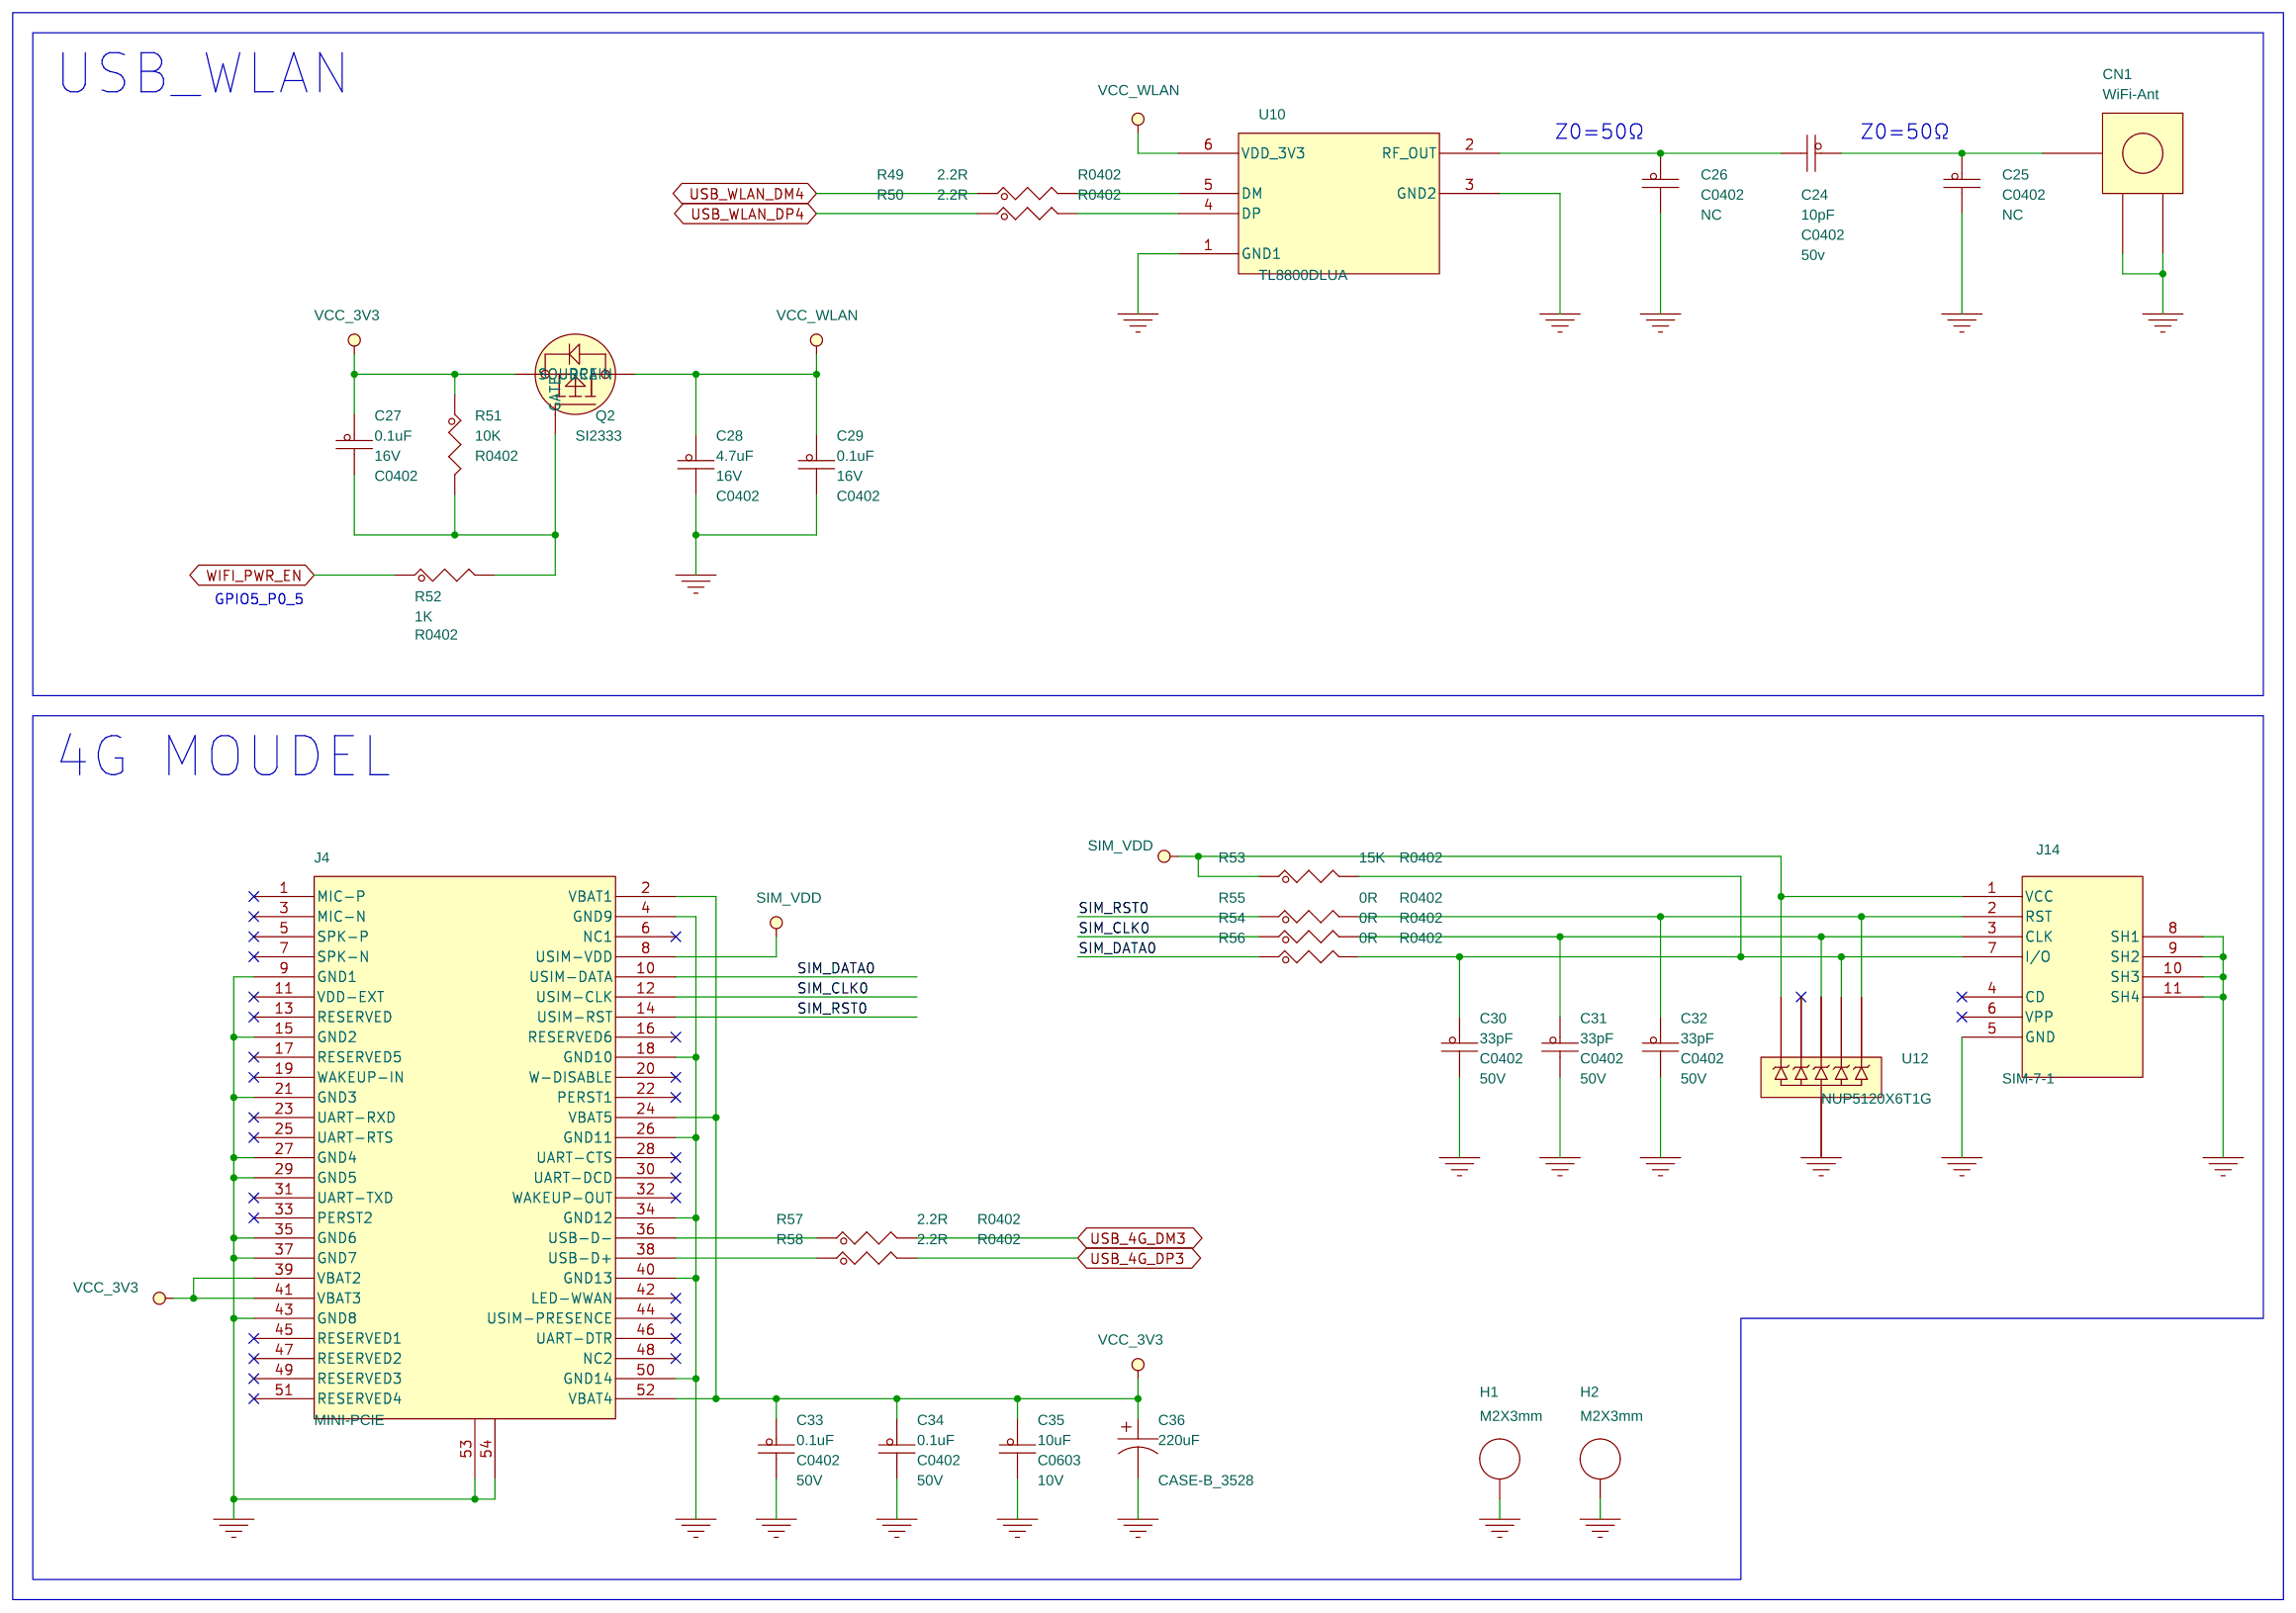
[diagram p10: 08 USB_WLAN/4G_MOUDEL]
12 09 MIPI CSI/RGB Display: size A3; note: MIPI CSI/RGB Display
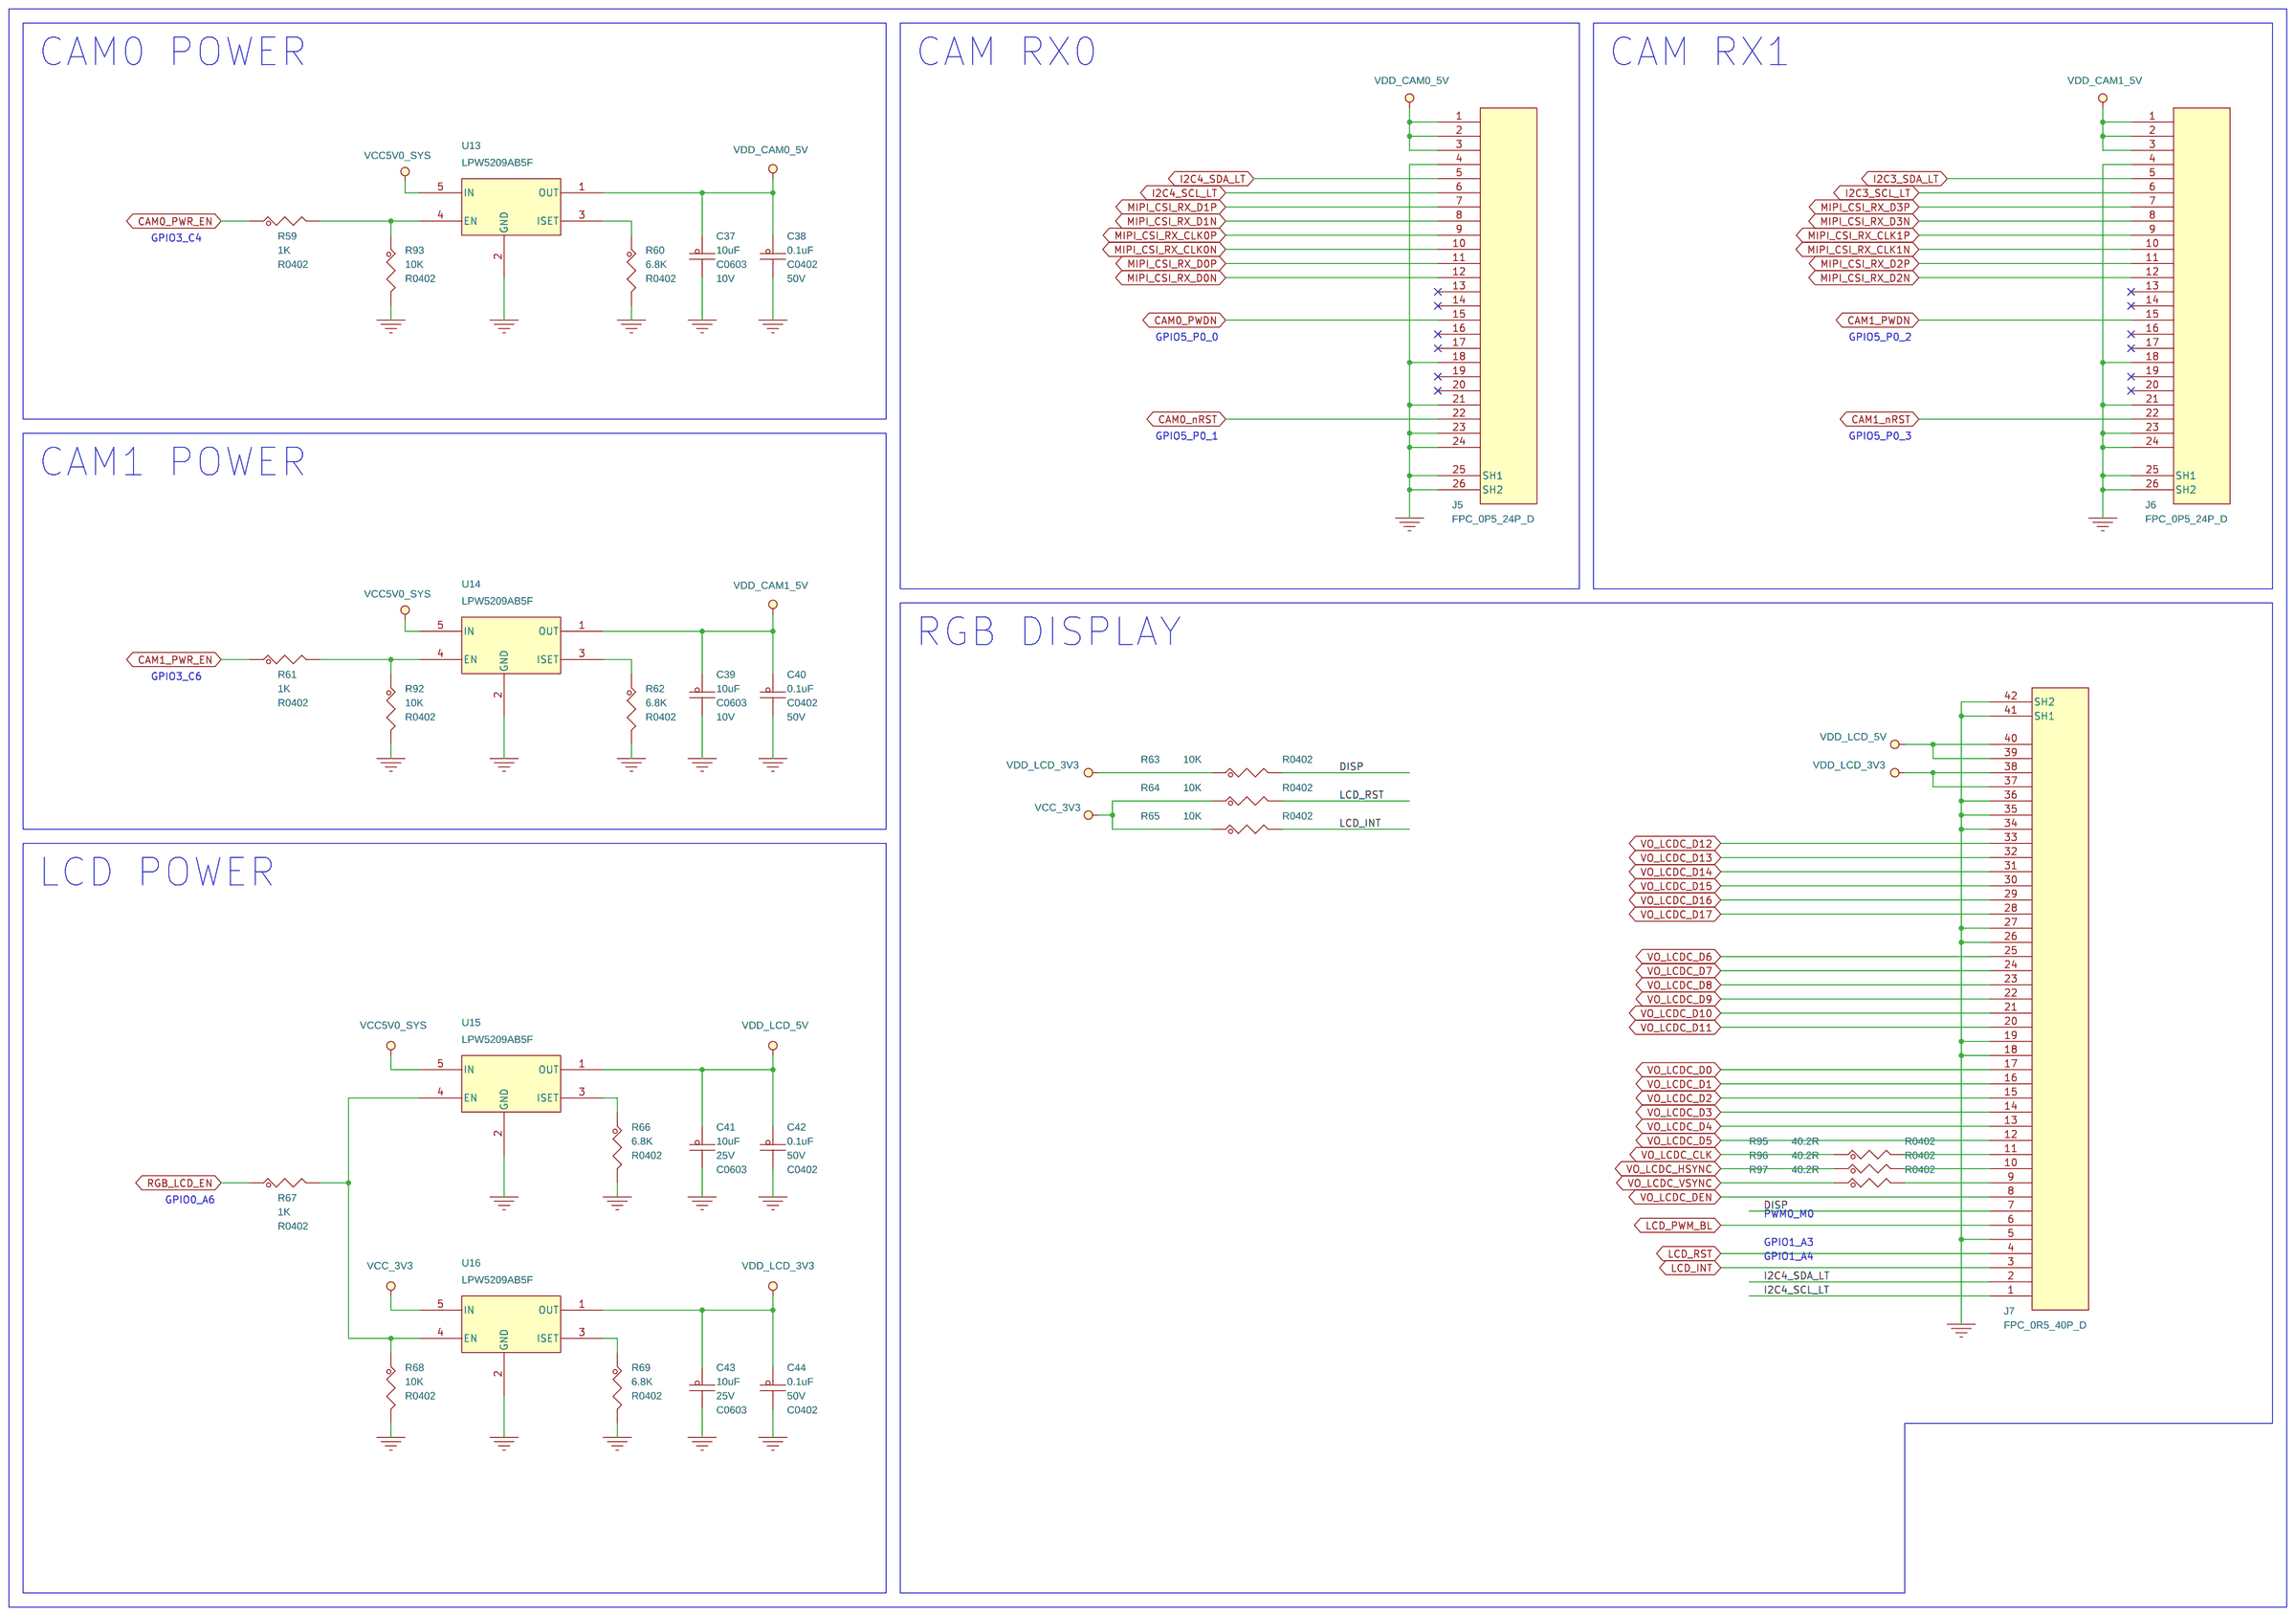
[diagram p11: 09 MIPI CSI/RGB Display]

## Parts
sheet 04 TYPE_C/Switch
C1  0.1uF  [C0402]
C2  0.1uF  [C0402]
C3  10uF  [C0603]
C4  0.1uF  [C0402]
C5  22pF  [C0402]
C6  10uF  [C0603]
C7  10uF  [C0603]
C8  0.1uF  [C0402]
D1  KLXES15AAA1  [ES0402]
D2  KLXES15AAA1  [ES0402]
D3  PESD5V0S1BA-N  [sod323_CA]
J1  TYPE-C  [TYPE-C-31-M-12]
L1  3.3uH  [l4520]
LED1  HS-0602-UR  [led_hs_0602_ur]
LED2  HS-0602-UG  [led_hs_0602_ur]
Q1  SS8050  [SOT23]
R1  4.7K  [R0402]
R2  2.2R  [R0402]
R3  2.2R  [R0402]
R4  5.1K  [R0402]
R5  5.1K  [R0402]
R6  12K  [R0402]
R7  22K  [R0402]
R8  4.7K  [R0402]
R9  2.2K  [R0402]
R10  100K  [R0402]
R11  1K  [R0402]
R12  0R  [R0402]
R13  22K  [R0402]
R14  NC  [R0402]
SS1  NPTH_M2.5  [NPTH_M2R5]
SS2  NPTH_M2.5  [NPTH_M2R5]
SS3  NPTH_M2.5  [NPTH_M2R5]
SS4  NPTH_M2.5  [NPTH_M2R5]
SW1  DSIC01LS-P  [SW2-6R20X3R50-SM]
U1  TS3USB30ERSWR  [UQFN_10]
U2  RY3430  [SOT23-5]
sheet 05 EVM Connector
U3  RV1106-35X35-HOLE-B-120P  [RV1106-35X35-HOLE-B-120P]  (sections A,B,C,D)
sheet 06 TF CARD/IO Expand
C9  0.1uF  [C0402]
C10  10uF  [C0402]
C11  0.1uF  [C0402]
C12  1uF  [C0402]
C13  1uF  [C0402]
C14  10uF  [C0402]
D4  KLXES15AAA1  [ES0402]
D5  KLXES15AAA1  [ES0402]
D6  KLXES15AAA1  [ES0402]
D7  KLXES15AAA1  [ES0402]
D8  KLXES15AAA1  [ES0402]
D9  KLXES15AAA1  [ES0402]
D10  KLXES15AAA1  [ES0402]
J2  TF_Card  [TFCARD]
R15  0R  [R0402]
R16  22R  [R0402]
R17  22R  [R0402]
R18  22R  [R0402]
R19  22R  [R0402]
R20  22R  [R0402]
R21  1K  [R0402]
R22  10K  [R0402]
R23  22R  [R0402]
R24  22R  [R0402]
R25  22R  [R0402]
R26  10K  [R0402]
R27  NC  [R0402]
R28  NC  [R0402]
R29  4.7K  [R0402]
R30  NC  [R0402]
R31  4.7K  [R0402]
R32  NC  [R0402]
R33  4.7K  [R0402]
R34  4.7K  [R0402]
R35  4.7K  [R0402]
R36  4.7K  [R0402]
U4  RS0104YTQE12  [QFN12L-0R4-2X2EP1R20X1R00]
U5  XL9535QF24  [QFN24-4X4EP2R70X2R70]
sheet 07 USB HUB
C15  NC  [C0402]
C16  NC  [C0402]
C17  10uF  [C0603]
C18  0.1uF  [C0402]
C19  0.1uF  [C0402]
C20  10uF  [C0402]
C21  0.1uF  [C0402]
C22  10uF  [C0603]
C23  0.1uF  [C0402]
J3  USB-A-D  [USB-A-D]  (sections A,B)
R37  2.2R  [R0402]
R38  2.2R  [R0402]
R39  NC  [R0402]
R40  2.2R  [R0402]
R41  100K  [R0402]
R42  2.2R  [R0402]
R43  100K  [R0402]
R44  NC  [R0402]
R45  0R  [R0402]
R46  3.4K  [R0402]
R47  10K  [R0402]
R48  3.4K  [R0402]
U6  CH334F  [QFN24]
U7  LPW5209AB5F  [SOT23-5]
U8  LPW5209AB5F  [SOT23-5]
U9  RCLAMP0524P  [USON_10]
Y1  12MHz  [3225]
sheet 08 USB_WLAN/4G_MOUDEL
C24  10pF  [C0402]
C25  NC  [C0402]
C26  NC  [C0402]
C27  0.1uF  [C0402]
C28  4.7uF  [C0402]
C29  0.1uF  [C0402]
C30  33pF  [C0402]
C31  33pF  [C0402]
C32  33pF  [C0402]
C33  0.1uF  [C0402]
C34  0.1uF  [C0402]
C35  10uF  [C0603]
C36  220uF  [CASE-B_3528]
CN1  WiFi-Ant  [UFL-3]
H1  M2X3mm  [t3r2-5r2_topsmt]
H2  M2X3mm  [t3r2-5r2_topsmt]
J4  MINI-PCIE  [pcie_52p]
J14  SIM-7-1  [nano_sim]
Q2  SI2333  [SOT23]
R49  2.2R  [R0402]
R50  2.2R  [R0402]
R51  10K  [R0402]
R52  1K  [R0402]
R53  15K  [R0402]
R54  0R  [R0402]
R55  0R  [R0402]
R56  0R  [R0402]
R57  2.2R  [R0402]
R58  2.2R  [R0402]
U10  TL8800DLUA  [SMD6-12R9X12R2]
U12  NUP5120X6T1G  [SOT563]
sheet 09 MIPI CSI/RGB Display
C37  10uF  [C0603]
C38  0.1uF  [C0402]
C39  10uF  [C0603]
C40  0.1uF  [C0402]
C41  10uF  [C0603]
C42  0.1uF  [C0402]
C43  10uF  [C0603]
C44  0.1uF  [C0402]
J5  FPC_0P5_24P_D  [fpc_24p_0p5]
J6  FPC_0P5_24P_D  [fpc_24p_0p5]
J7  FPC_0R5_40P_D  [FPC-40P-0P5]
R59  1K  [R0402]
R60  6.8K  [R0402]
R61  1K  [R0402]
R62  6.8K  [R0402]
R63  10K  [R0402]
R64  10K  [R0402]
R65  10K  [R0402]
R66  6.8K  [R0402]
R67  1K  [R0402]
R68  10K  [R0402]
R69  6.8K  [R0402]
R92  10K  [R0402]
R93  10K  [R0402]
R95  40.2R  [R0402]
R96  40.2R  [R0402]
R97  40.2R  [R0402]
U13  LPW5209AB5F  [SOT23-5]
U14  LPW5209AB5F  [SOT23-5]
U15  LPW5209AB5F  [SOT23-5]
U16  LPW5209AB5F  [SOT23-5]
sheet 10 ETH
C45  22nF  [C0402]
C46  22nF  [C0402]
C47  1nF  [C0805]
J8  HR911105A  [RJ45]
Q3  SS8050  [SOT23]
Q4  SS8050  [SOT23]
R70  0R  [R0402]
R71  0R  [R0402]
R72  0R  [R0402]
R73  0R  [R0402]
R74  1K  [R0402]
R75  1K  [R0402]
R76  1K  [R0402]
R77  1M  [R0805]
R78  1K  [R0402]
sheet 11 MIC/SPK
C48  NC  [C0402]
C49  NC  [C0402]
C50  NC  [C0402]
C51  NC  [C0402]
C52  10uF  [C0603]
C53  0.1uF  [C0402]
C54  0.22uF  [C0402]
C55  1uF  [C0402]
J9  YTC-A1251-02AB  [YTC-A1251-02AB]
J10  YTC-A1251-02AB  [YTC-A1251-02AB]
J11  YTC-A1251-02AB  [YTC-A1251-02AB]
R79  NC  [R0402]
R80  NC  [R0402]
R81  NC  [R0402]
R82  NC  [R0402]
R83  NC  [R0402]
R84  NC  [R0402]
R85  20K  [R0402]
R86  100K  [R0402]
U17  8002A  [SOP8]
sheet 12 DEBUG/PIN OUT/KEY
D11  KLXES15AAA1  [ES0402]
D12  KLXES15AAA1  [ES0402]
D13  KLXES15AAA1  [ES0402]
J12  HDR2X15-2R54-TM-VM  [HDR2X15-2R54-TM-VM]
J13  1X3PIN-M  [DIP_3p_2p54]
R87  100R  [R0402]
R88  510R  [R0402]
R89  510R  [R0402]
R90  100R  [R0402]
R91  100R  [R0402]
R94  10K  [R0402]
SW2  SW_PB_ESW  [SW4-4R20X3R25-SM]
SW3  SW_PB_ESW  [SW4-4R20X3R25-SM]
SW4  SW_PB_ESW  [SW4-4R20X3R25-SM]
Z1  KLXES15AAA1  [ES0402]
Z2  KLXES15AAA1  [ES0402]

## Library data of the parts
C1 C2 C53 = CAP_NP: voltage: 50V; 规格: 贴片电容0.1uF 10% 50V X5R 0402; 规格编号: 0402X104K500NT; 规格书: 风华电容.pdf; 价格: 0.029826; 类别: 贴片电容0402; 品牌: 风华; 生命周期: 量产; 条码: EBF29060118
C3 C6 C7 C35 C37 C39 = CAP_NP: Voltage: 10V; 规格: 贴片电容10uF 10% 10V X5R 0603; 规格编号: 0603X106K100NT; 规格书: 风华电容.pdf; 价格: 0.081215; 类别: 贴片电容0603; 品牌: 风华; 生命周期: 量产; 条码: EBF29060126
C4 C8 C9 C19 C33 C34 C38 C40 = CAP_NP: Voltage: 50V; 规格: 贴片电容0.1uF 10% 50V X5R 0402; 规格编号: 0402X104K500NT; 规格书: 风华电容.pdf; 价格: 0.029826; 类别: 贴片电容0402; 品牌: 风华; 生命周期: 量产; 条码: EBF29060118
C5 = CAP_NP: Voltage: 50V; 规格: 贴片电容22pF 5% 50V C0G 0402; 规格编号: 0402CG220J500NT; 规格书: 三星电容.pdf; 价格: 0.004645; 类别: 贴片电容0402; 品牌: 三星; 生命周期: 量产; 条码: EBF29060220
D1 D2 D4-D13 Z1 Z2 = DIODE_BI-DIR_TRIG: 规格: 用于 USB3.0、HDMI 0.5pF、5V、±15kV ESD 保护二极管; 规格书: KLXES15AAA1.pdf; 价格: 0.09719; 类别: 贴片ESD; 品牌: 永裕泰; 生命周期: 量产; 条码: EBF29140063
D3 = DIODE_BI-DIR_TRIG: 规格: 防静电保护ESD二极管 箝位电压21V 击穿电压6V 反向关断电压5V; 规格书: 伯恩半导体-PESD5V0S1BA-N.pdf; 价格: 0.196644; 类别: 贴片ESD; 品牌: 伯恩半导体; 生命周期: 量产; 条码: EBF29140021
J1 = TYPE-C-31-M-12: 规格: Type-C母座 16P 贴片 USB-2.0 插座 高清传输接口 4固定插脚 双向; 规格书: TYPE-C-31-M-12母座贴片.pdf; 价格: 1.06; 类别: USB接口; 品牌: 韩国韩容; 生命周期: 量产; 条码: EBF29040004
L1 = IND: 规格: 贴片电感3.3uH ±20% 3A 直流电阻69mΩ; 规格编号: TMPC0402HP-3R3MG-Z02; 规格书: 台庆-功率电感.pdf; 价格: 1.5992; 类别: 贴片电感0402; 品牌: 台庆; 生命周期: 量产; 条码: EBF29050040
LED1 = LED: 规格: 侧贴0602LED 红色; 规格书: HS-0602-UR.pdf; 类别: 侧贴发光LED; 品牌: 鸿之森; 生命周期: 量产; 条码: EBF29140054
LED2 = LED: 规格: 正向电压(VF)：3.2V 工作电流：5mA 功率：80mW 绿色; 规格书: HS-0602-UG.pdf; 价格: 0.068705; 类别: 侧贴发光LED; 品牌: 鸿之森; 生命周期: 量产; 条码: EBF29140060
Q1 Q3 Q4 = NPN: 规格: 贴片三极管SS8050 集电极电流1.5A 额定功率300mW NPN; 规格书: 江苏长电-SS8050Y1.pdf; 价格: 0.086744; 类别: 贴片三极管SOT-23; 品牌: 江苏长电; 生命周期: 量产; 丝印: Y1; 条码: EBF29090001
R1 R8 R29 R31 R33-R36 = RES: 规格: 贴片电阻4.7K 1% 1/16W 0402; 规格编号: RI0402L4701FT; 规格书: 合科泰-RI系列电阻.pdf; 类别: 贴片电阻0402; 品牌: 合科泰; 生命周期: 量产; 条码: EBF29070047
R2 R3 R37 R38 R40 R42 R49 R50 R57 R58 = RES: 规格: 贴片电阻2.2R 1% 1/16W 0402; 规格编号: 0402WGF220KTCE; 规格书: 厚声-无铅厚膜电阻.pdf; 价格: 0.003072; 类别: 贴片电阻0402; 品牌: 厚声; 生命周期: 量产; 条码: EBF29070280
R4 R5 = RES: 规格: 贴片电阻5.1K 1% 1/16W 0402; 规格编号: 0402F5101BV1906130014; 类别: 贴片电阻0402; 品牌: VO; 生命周期: 量产; 条码: EBF29070258
R6 = RES: 规格: 贴片电阻12K 1% 1/16W 0402; 规格编号: RI0402L1202FT; 规格书: 合科泰-RI系列电阻.pdf; 类别: 贴片电阻0402; 品牌: 合科泰; 生命周期: 量产; 条码: EBF29070255
R7 R13 = RES: 备注: 6750邮票孔; 规格: 贴片电阻22K 1% 1/16W 0402; 规格编号: 0402WGF2202TCE; 规格书: 厚声-无铅厚膜电阻.pdf; 价格: 0.003345; 类别: 贴片电阻0402; 品牌: 厚声; 生命周期: 量产; 条码: EBFCIS230704154430
R9 = RES: 规格: 贴片电阻2.2K 1% 1/16W 0402; 规格编号: RI0402L2201FT; 规格书: 合科泰-RI系列电阻.pdf; 类别: 贴片电阻0402; 品牌: 合科泰; 生命周期: 量产; 条码: EBF29070051
R10 R41 R43 R86 = RES: 规格: 贴片电阻100K 1% 1/16W 0402; 规格编号: RI0402L1003FT; 规格书: 合科泰-RI系列电阻.pdf; 类别: 贴片电阻0402; 品牌: 合科泰; 生命周期: 量产; 条码: EBF29070054
R11 R21 R52 R59 R61 R67 R74-R76 R78 = RES: 规格: 贴片电阻1K 1% 1/16W 0402; 规格编号: RI0402L1001FT; 规格书: 合科泰-RI系列电阻.pdf; 类别: 贴片电阻0402; 品牌: 合科泰; 生命周期: 量产; 条码: EBF29070050
R12 R15 R45 R54-R56 R70-R73 = RES: 规格: 贴片电阻0R 1% 1/16W 0402; 规格编号: RI0402L000FT; 规格书: 合科泰-RI系列电阻.pdf; 类别: 贴片电阻0402; 品牌: 合科泰; 生命周期: 量产; 条码: EBF29070049
R14 R27 R28 R30 R32 R39 R44 R79-R84 = RES: 规格: 贴片电阻NC 预留; 类别: 贴片电阻0402; 条码: EBF29070087
SS1-SS4 = SPACER: 规格编号: M2.5螺丝孔_无铜; 类别: M2.5螺丝孔; 品牌: 野火; 生命周期: 量产; 条码: EBFCIS220926102855
SW1 = SW01: 备注: RV1106G邮票孔底板; 规格: 贴片拨码开关 黑色 单刀单掷 凸起式 1位; 规格书: 中国星坤_DSIC01LS-P.pdf; 价格: 1.6; 类别: 贴片拨码开关; 品牌: 中国星坤; 生命周期: 量产; 条码: EBFCIS240624173356
U1 = TS3USB30ERSWR: 规格: 功能：USB 开关 电路2x2：1 导通电阻（最大值）10 欧姆 电压源：单电源 电压电源单/双（±）：3 V~4.3V 电流电源：1μA 工作温度：-40°C~85°C; 规格书: ts3usb30e.pdf; 价格: 4.83; 类别: 复用器; 品牌: 德州仪器; 生命周期: 量产; 条码: EBF29240001
U2 = MT3520B: 备注: RV1103G IPC摄像头; 规格: DC-DC电源芯片 输入电压：2.5V 至 5.5V 低压差100%占空比操作 高达3A的输出电流 低静态电流：40μA 频率：1.2MHz; 规格书: 蕊源_RY3430.pdf; 价格: 1.035; 类别: 电源管理-DCDC; 品牌: 蕊源; 生命周期: 量产; 条码: EBFCIS240506091246
U3 = RV1106G_CORE_120P: 备注: RV1106G 邮票孔核心板; 规格: RV1106G 邮票孔底板 35x35mm; 类别: 邮票孔底板封装; 品牌: 野火; 生命周期: 量产; 条码: EBFCIS240614172505
C10 C20 = CAP_NP: HEIGHT: 1MM; MFG_NAME01: Samsung; MFG_PN01: CL10A226MQ8NRNE; ROHS: Yes; Tolerance: 20%; VOLTAGE: 10V; voltage rating: 10V; 规格: 贴片电容10uF 20% 10V X5R 0402; 规格编号: CL05A106MP8NUB8; 规格书: 三星电容.pdf; 价格: 0.518415; 类别: 贴片电容0402; 品牌: 三星; 生命周期: 量产; 条码: EBF29060247
C11 C18 C21 C23 C42 C44 = CAP_NP: HEIGHT: 1MM; MFG_NAME01: Samsung; MFG_PN01: CL10A226MQ8NRNE; ROHS: Yes; Tolerance: 20%; VOLTAGE: 50V; voltage rating: 50V; 规格: 贴片电容0.1uF 10% 50V X5R 0402; 规格编号: 0402X104K500NT; 规格书: 风华电容.pdf; 价格: 0.029826; 类别: 贴片电容0402; 品牌: 风华; 生命周期: 量产; 条码: EBF29060118
C12 C13 = CAP_NP: Voltage: 10V; 规格: 贴片电容1uF 10% 10V X5R 0402; 规格编号: 0402X105K100NT; 规格书: 风华电容.pdf; 价格: 0.01191; 类别: 贴片电容0402; 品牌: 风华; 生命周期: 量产; 条码: EBF29060121
C14 = CAP_NP: Voltage: 10V; 规格: 贴片电容10uF 20% 10V X5R 0402; 规格编号: CL05A106MP8NUB8; 规格书: 三星电容.pdf; 价格: 0.518415; 类别: 贴片电容0402; 品牌: 三星; 生命周期: 量产; 条码: EBF29060247
J2 = TF_Card: 规格: MICRO SD 卡座 TF T-Flash 外焊 双压片 自弹贴片; 规格编号: TF-015; 规格书: 硕方-TF-015.pdf; 价格: 0.48; 可替代料: EBF29040003; 类别: SD卡连接器; 品牌: 硕方; 生命周期: 量产; 条码: EBF29040003
R16-R20 R23-R25 = RES: 规格: 贴片电阻22R 1% 1/16W 0402; 规格编号: RI0402L22R0FT; 规格书: 合科泰-RI系列电阻.pdf; 类别: 贴片电阻0402; 品牌: 合科泰; 生命周期: 量产; 条码: EBF29070181
R22 R26 R47 R51 R63-R65 R68 R92-R94 = RES: 规格: 贴片电阻10K 1% 1/16W 0402; 规格编号: 0402WGF1002TCE; 规格书: 厚声-无铅厚膜电阻.pdf; 价格: 0.002773; 类别: 贴片电阻0402; 品牌: 厚声; 生命周期: 量产; 条码: EBF29070046
U4 = RS0104YTQE12: 备注: 全志H618; 规格: 具有自动方向检测和4位双向电压电平转换器 应用与SMBus总线与I2C与UART总线 速率：24Mbps（推挽）2Mbps（开漏）; 规格书: RUNIC(润石)_RS0104YTQE12.pdf; 价格: 1.46; 类别: 电平转换器; 品牌: RUNIC(润石); 生命周期: 量产; 条码: EBFCIS231211143110
U5 = XL9535QF24: 备注: RK3588一体板 接口拓展芯片; 规格: I2C接口 16个双向输入输出引脚 支持中断输出 工作电压2.3V~5.5V; 规格书: 信路达_XL9535.pdf; 价格: 1.87; 类别: IO拓展; 品牌: 信路达; 生命周期: 量产; 条码: EBFCIS230807164638
C15 C16 C25 C26 C48-C51 = CAP_NP: 规格: 贴片电容NC 预留; 类别: 贴片电容0402; 条码: EBF29060149
C17 C22 C41 C43 = CAP_NP: HEIGHT: 1MM; MFG_NAME01: Samsung; MFG_PN01: CL10A226MQ8NRNE; ROHS: Yes; Tolerance: 20%; VOLTAGE: 10V; voltage rating: 25V; 规格: 贴片电容10uF 10% 10V X5R 0603; 规格编号: 0603X106K100NT; 规格书: 风华电容.pdf; 价格: 0.081215; 类别: 贴片电容0603; 品牌: 风华; 生命周期: 量产; 条码: EBF29060126
J3 = USB-A-D: 规格: 双层USB接口 A型接口 90度双排弯插脚 AF母座 焊接式; 规格编号: 907-111A1012D10200; 规格书: 精拓金-双层USB.pdf; 价格: 0.22; 类别: USB接口; 品牌: 精拓金; 生命周期: 量产; 条码: EBF29020027
R46 R48 = RES: 规格: 贴片电阻3.4K 1% 1/16W 0402; 规格编号: RI0402L3401FT; 规格书: 合科泰-RI系列电阻.pdf; 类别: 贴片电阻0402; 品牌: 合科泰; 生命周期: 量产; 条码: EBF29070186
U6 = CH334F: 规格: USB HUB芯片 工作电压3.3V 5V 协议类别USB2.0 支持高速(480Mbps) 全速(12Mbps)和低速(1.5Mbps)模式; 规格书: 南京沁恒_CH334F.pdf; 价格: 2.09; 类别: USB芯片; 品牌: 南京沁恒; 生命周期: 量产; 条码: EBFCIS221222095807
U7 U8 U13-U16 = LPW5209AB5F: 规格: 集成电源开关 导通电阻：80mΩ 最大可设置保护电流：2.1A 输入电压：2.5V~6V 静态电流：30uA 其他功能：软启动、短路保护、热保护; 规格书: 微源半导体_LPW5209AB5F.pdf; 价格: 0.468063; 类别: 功率开关; 品牌: 微源半导体; 生命周期: 量产; 条码: EBF29280015
U9 = RCLAMP0524P: 规格: TVS二极管 箝位电压17V 击穿电压8V 反向关断电压5V; 规格书: 台舟-RCLAMP0524P.pdf; 价格: 0.185957; 类别: 贴片四路ESD; 品牌: 台舟; 生命周期: 量产; 条码: EBF29140046
Y1 = CRYSTAL_4P: 规格: 无源晶振12MHZ 80Ω 20pF 3225; 规格编号: X322512MSB4SI; 规格书: 扬兴科技-贴片晶振.pdf; 价格: 0.327763; 可替代料: EBF29100013; 类别: 贴片晶振 3225; 品牌: 扬兴科技; 生命周期: 量产; 条码: EBF29100013
C24 = CAP_NP: Voltage: 50v; 规格: 贴片电容10pF 5% 50V C0G 0402; 规格编号: 0402CG100J500NT; 规格书: 风华电容.pdf; 价格: 0.00453; 类别: 贴片电容0402; 品牌: 风华; 生命周期: 量产; 条码: EBF29060127
C27 C29 = CAP_NP: HEIGHT: 1MM; MFG_NAME01: Samsung; MFG_PN01: CL10A226MQ8NRNE; ROHS: Yes; Tolerance: 20%; VOLTAGE: 50V; voltage rating: 16V; 规格: 贴片电容0.1uF 10% 50V X5R 0402; 规格编号: 0402X104K500NT; 规格书: 风华电容.pdf; 价格: 0.029826; 类别: 贴片电容0402; 品牌: 风华; 生命周期: 量产; 条码: EBF29060118
C28 = CAP_NP: HEIGHT: 1MM; MFG_NAME01: Samsung; MFG_PN01: CL10A226MQ8NRNE; ROHS: Yes; Tolerance: 20%; VOLTAGE: 10V; voltage rating: 16V; 规格: 贴片电容4.7uF 10% 10V X5R 0402; 规格编号: CC0402KRX5R6BB475; 规格书: 国巨-贴片电容.pdf; 价格: 0.059058; 类别: 贴片电容0402; 品牌: 国巨; 生命周期: 量产; 条码: EBF29060248
C30-C32 = CAP_NP: Voltage: 50V; 规格: 贴片电容33pF 5% 50V 0402; 规格编号: 0402CG330J500NT; 规格书: 风华电容.pdf; 类别: 贴片电容0402; 品牌: 风华; 生命周期: 量产; 条码: EBF29060298
C36 = CAP: voltage: 6.3V; 规格: 贴片电容220uF 20% 6.3V 坦电容 CASE-B_3528; 规格编号: TLJB227M006R0500; 规格书: AVX_贴片坦电容.pdf; 价格: 1.28; 类别: 贴片坦电容; 品牌: AVX; 生命周期: 量产; 条码: EBF29060264
CN1 = WIFI_ANT: 规格: RF同轴连接器（天线座）; 规格编号: KH-IPEX-K501-29; 规格书: 金航标-天线座.pdf; 价格: 0.247224; 类别: WiFi天线座; 品牌: 金航标; 生命周期: 量产; 条码: EBF430005
H1 H2 = SPACER: 规格: SMT贴片螺母M2 高度3MM 台阶外径：4.5MM 整体高度：4.5MM 焊接孔外径：3MM; 规格编号: ZIY01-001; 规格书: 雄和远景_SMTWE2040CTJ.pdf; 类别: 贴片螺母; 品牌: 雄和远景; 生命周期: 量产; 条码: EBF500026
J4 = MINI-PCIE: 规格: MINI PCIE插座 引脚数：52P; 规格编号: PCIE-52P56H; 规格书: XUNPU(讯普)_52PMINIPCIE插座.pdf; 价格: 1.935; 可替代料: EBF29040055; 类别: 金手指连接器; 品牌: 讯普; 生命周期: 量产; 条码: EBF29040055
J14 = SIM-7-1: 规格: nano sim卡座; 规格编号: HYC63-SIM07-137; 规格书: 华宇创_NANOSIMPUSH1.37H带CDPIN带柱.pdf; 价格: 1.48; 可替代料: EBF29040054; 类别: SIM卡座连接器; 品牌: 华宇创; 生命周期: 量产; 条码: EBF29040054
Q2 = MOSFET_P: HEIGHT: 1.12MM; MFG_NAME01: INTERNATIONAL RECTIFIER; MFG_PN01: IRLML6401TRPBF; ROHS: Yes; 规格: P沟道MOS 导通电阻28mΩ@4.5V5A 12V7.1A 阈值电压1V@250uA; 规格书: SI2333-TP.pdf; 价格: 0.586115; 类别: P-MOS; 品牌: 伯恩半导体; 生命周期: 量产; 条码: EBF29280020
R53 = RES: 规格: 贴片电阻15K 1% 1/16W 0402; 规格编号: RI0402L1502FT; 规格书: 合科泰-RI系列电阻.pdf; 类别: 贴片电阻0402; 品牌: 合科泰; 生命周期: 量产; 条码: EBF29070222
U10 = TL8800DLUA: 备注: RK3528 邮票孔底板使用; 规格: WiFi6模块 接口类型：USB 工作电压：3.3V 传输速率可达286.8Mbps 工作频率：2.4G+5.8G; 规格书: 创凌智联_TL8800DLUA.pdf; 价格: 5; 类别: WiFi模块; 品牌: 创凌智联; 生命周期: 量产; 丝印: AIC8800DL; 条码: EBFCIS240330175655
U12 = NUP5120-D: 规格: 防静电保护ESD二极管 击穿电压6.2V 反向关断电压5V 封装SOT-523; 规格书: 安森美_NUP5120X6T1G.pdf; 价格: 0.39; 类别: 贴片ESD; 品牌: 安森美; 生命周期: 量产; 条码: EBF29140034
J5 J6 = FPC-24P: 规格: FPC连接器 针脚数24 间距0.5mmm 下接 卧贴 翻盖式; 规格编号: AFC01-S24FCA-00; 规格书: 钜硕电子-FPC间距0.5mm.pdf; 价格: 0.368739; 可替代料: EBF29040059; 类别: FPC连接器; 品牌: 钜硕电子; 生命周期: 量产; 条码: EBF29040059
J7 = FPC-40P: 规格: FFC-FPC连接器 针脚数40 间距0.5mm 锁定特性0.5mm 高度2mm 翻盖式 下接 卧贴; 规格编号: F0502-B-40-20T-R; 规格书: 台湾兴飞FPC0.5MM间距翻盖式下接.pdf; 价格: 0.56; 可替代料: EBF29040001; 类别: FPC连接器; 品牌: 台湾兴飞; 生命周期: 量产; 条码: EBF29040001
R60 R62 R66 R69 = RES: 规格: 贴片电阻6.8K 1% 1/16W 0402; 规格编号: RI0402L6801FT; 规格书: 合科泰-RI系列电阻.pdf; 类别: 贴片电阻0402; 品牌: 合科泰; 生命周期: 量产; 条码: EBF29070052
R95-R97 = RES: 规格: 贴片电阻40.2R 1% 1/16W 0402; 规格编号: 0402WGF402JTCE; 规格书: 厚声-无铅厚膜电阻.pdf; 价格: 0.003484; 类别: 贴片电阻0402; 品牌: 厚声; 生命周期: 量产; 条码: EBF29070232
C45 C46 = CAP_NP: voltage: 50V; 规格: 贴片电容22nF 10% 50V X7R 0402; 规格编号: 0402B223K500NT; 规格书: 风华电容.pdf; 价格: 0.009905; 类别: 贴片电容0402; 品牌: 风华; 生命周期: 量产; 条码: EBF29060246
C47 = CAP_NP: voltage: 1kv; 规格: 贴片电容1nF 10% 1kV X7R 0805; 规格编号: 0805B102K102CT; 规格书: 华新科0805系列高压贴片电容.pdf; 价格: 0.083527; 类别: 贴片电容0805; 品牌: 华新科; 生命周期: 量产; 条码: EBF29060304
J8 = RJ45_HR961160C: 规格: 以太网连接器RJ45 引脚数12 LED灯黄绿; 规格书: 汉仁-RJ45-带LED灯.pdf; 价格: 6.46; 可替代料: EBF29020022; 类别: 网口; 品牌: 汉仁; 生命周期: 量产; 条码: EBF29020022
R77 = RES: 规格: 贴片电阻1M 1% 1/8W 0805; 规格编号: AC0805FR-071ML; 规格书: YAGEO国巨厚膜无铅电阻.pdf; 价格: 0.02396; 类别: 贴片电阻0805; 品牌: 国巨; 生命周期: 量产; 条码: EBF29070294
C52 = CAP_NP: voltage: 10V; 规格: 贴片电容10uF 10% 10V X5R 0603; 规格编号: 0603X106K100NT; 规格书: 风华电容.pdf; 价格: 0.081215; 类别: 贴片电容0603; 品牌: 风华; 生命周期: 量产; 条码: EBF29060126
C54 = CAP_NP: voltage: 50V; 规格: 贴片电容0.22uF 20% 50V X5R 0402; 规格编号: UMK105BJ224MV-F; 规格书: 太诱-贴片电容.pdf; 价格: 0.074942; 类别: 贴片电容0402; 品牌: 太诱; 生命周期: 量产; 条码: EBF29060266
C55 = CAP_NP: voltage: 10V; 规格: 贴片电容1uF 10% 10V X5R 0402; 规格编号: 0402X105K100NT; 规格书: 风华电容.pdf; 价格: 0.01191; 类别: 贴片电容0402; 品牌: 风华; 生命周期: 量产; 条码: EBF29060121
J9-J11 = 1X2PIN_SH: 备注: RV1103G IPC摄像头; 规格: 间距=1.25mm 立式贴片 镀锡 2P 针座连接器 母座; 规格书: 怡远_YTC-A1251-02AB.pdf; 价格: 0.09197; 类别: 1.25连接器; 品牌: 怡远; 生命周期: 量产; 条码: EBFCIS240506164620
R85 = RES: 规格: 贴片电阻20K 1% 1/16W 0402; 规格编号: 0402WGF2002TCE; 规格书: 厚声-无铅厚膜电阻.pdf; 价格: 0.002473; 类别: 贴片电阻0402; 品牌: 厚声; 生命周期: 量产; 条码: EBF29070223
U17 = 8002A: 规格: 桥式音频功率放大器 输出功率高（4Ω 1KHz）宽工作电压范围2.2V-5.5V 输出不需要外接耦合电容或上举电容 缓冲网络 反馈电阻; 规格书: 英锐芯_8002A.pdf; 价格: 0.475235; 类别: 音频芯片; 品牌: 英锐芯; 生命周期: 量产; 条码: EBF29200006
J12 = 2X15PIN: 备注: 通用; 规格: 蓝色直插双排排针 总PIN数30 间距2.54mm; 规格编号: HDR2X15-2R54-TM-VM-BLUE; 规格书: 州日_HDR2X15-2R54-TM-VM-BLACK.pdf; 价格: 0.3; 类别: 2.54mm直插双排排针; 品牌: 州日; 生命周期: 量产; 条码: EBFCIS230713090254
J13 = 1X3PIN: 规格: 排针 总PIN数3 间距2.54mm 直插; 规格书: 州日_单排针_直插_2P54.pdf; 类别: 2.54mm直插单排排针; 生命周期: 量产; 条码: EBF29020039
R87 R90 R91 = RES: HEIGHT: 0.4MM; MFG_NAME01: PANASONIC; MFG_PN01: ERJ-2GEJ105X; ROHS: Yes; Tolerance: 5%; 规格: 贴片电阻100R 1% 1/16W 0402; 规格编号: RI0402L1000FT; 规格书: 合科泰-RI系列电阻.pdf; 类别: 贴片电阻0402; 品牌: 合科泰; 生命周期: 量产; 条码: EBF29070053
R88 R89 = RES: 规格: 贴片电阻510R 1% 1/16W 0402; 规格编号: 0402WGF5100TCE; 规格书: 厚声-无铅厚膜电阻.pdf; 价格: 0.003791; 类别: 贴片电阻0402; 品牌: 厚声; 生命周期: 量产; 条码: EBF29070293
SW2-SW4 = SW_PB_ESW: 备注: 修正封装; 规格: 3×4×2.5 160gf 轻触开关 白色; 规格编号: TS-1089U-AR02526; 规格书: 讯普3×4×2.5160GF轻触开.pdf; 价格: 0.168282; 类别: 贴片轻触开关; 品牌: 讯普; 生命周期: 量产; 条码: EBF29310006

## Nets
GND: C1.2 C2.2 C3.2 C4.2 C6.2 C7.2 C8.2 C9.2 C10.2 C11.2 C12.2 C13.2 C14.2 C15.2 C16.1 C17.2 C18.2 C19.2 C20.2 C21.2 C22.2 C23.2 C25.2 C26.2 C28.2 C29.2 C30.2 C31.2 C32.2 C33.2 C34.2 C35.2 C36.2 C37.2 C38.2 C39.2 C40.2 C41.2 C42.2 C43.2 C44.2 C45.2 C46.2 C47.2 C48.2 C49.2 C52.2 C53.2 C55.2 CN1.2 CN1.3 D1.1 D2.1 D3.2 D4.2 D5.2 D6.2 D7.2 D8.2 D9.2 D10.2 D11.1 D12.1 D13.1 H1.1(NC) H2.1(NC) J1.A1(GND1) J1.A12(GND2) J1.B1(GND4) J1.B12(GND3) J1.C1(SH1) J1.C2(SH2) J1.C3(SH3) J1.C4(SH4) J2.6(VSS) J2.10(GND10) J2.11(GND11) J2.12(GND12) J2.13(GND13) J3.4(GND) J3.5(SH1) J3.6(SH2) J3.10(GND) J3.11(SH1) J3.12(SH2) J4.4(GND9) J4.9(GND1) J4.15(GND2) J4.18(GND10) J4.21(GND3) J4.26(GND11) J4.27(GND4) J4.29(GND5) J4.34(GND12) J4.35(GND6) J4.37(GND7) J4.40(GND13) J4.43(GND8) J4.50(GND14) J4.53 J4.54 J5.4 J5.18 J5.21 J5.23 J5.24 J5.25(SH1) J5.26(SH2) J6.4 J6.18 J6.21 J6.23 J6.24 J6.25(SH1) J6.26(SH2) J7.5 J7.18 J7.19 J7.26 J7.27 J7.34 J7.35 J7.36 J7.41(SH1) J7.42(SH2) J8.8(CHS_GND) J9.3(SH1) J9.4(SH2) J10.3(SH1) J10.4(SH2) J11.3(SH1) J11.4(SH2) J12.6 J12.9 J12.14 J12.20 J12.25 J12.30 J13.1 J14.5(GND) J14.8(SH1) J14.9(SH2) J14.10(SH3) J14.11(SH4) LED1.1(CATHODE) Q1.2(EMITTER) Q3.2(EMITTER) Q4.2(EMITTER) R4.2 R5.2 R7.2 R13.2 R44.2 R46.2 R47.2 R48.2 R60.2 R62.2 R66.2 R68.2 R69.2 R77.2 R83.2 R84.2 R92.2 R93.2 SW1.2(B1) SW2.1(A1) SW2.2(A2) SW3.1(A1) SW3.2(A2) SW4.1(A1) SW4.2(A2) U1.4(GND) U1.8(~{OE}) U2.2(GND) U3.1(GND0) U3.11(GND1) U3.24(GND2) U3.27(GND3) U3.30(GND4) U3.39(GND5) U3.42(GND6) U3.45(GND7) U3.48(GND8) U3.51(GND9) U3.54(GND10) U3.57(GND11) U3.60(GND13) U3.61(GND14) U3.62(GND15) U3.63(GND16) U3.64(GND17) U3.67(GND18) U3.69(GND19) U3.71(GND20) U3.74(GND21) U3.77(GND22) U3.85(GND23) U3.88(GND24) U3.90(GND25) U3.92(GND26) U3.95(GND27) U3.98(GND28) U3.101(GND29) U3.110(GND30) U3.118(GND12) U3.120(GND31) U4.5(GND) U4.13(EP) U5.9(GND) U5.25(EPAD) U6.25(VSS) U7.2(GND) U8.2(GND) U9.3(GND1) U9.8(GND2) U10.1(GND1) U10.3(GND2) U12.2 U13.2(GND) U14.2(GND) U15.2(GND) U16.2(GND) U17.7(GND) Y1.2(GND1) Y1.4(GND2) Z1.2 Z2.2
VCC3V3_SD: C10.1 C11.1 J2.4(VDD) R15.2
VCC5V0_SYS: C2.1 C3.1 C4.1 C52.1 C53.1 D3.1 J1.A4(VBUS1) J1.A9(VBUS2) J1.B4(VBUS4) J1.B9(VBUS3) J12.2 J12.4 R6.1 R8.1 R12.1 U2.4(VIN) U3.65(Power_5V_IN0) U3.66(Power_5V_IN1) U7.5(IN) U8.5(IN) U13.5(IN) U14.5(IN) U15.5(IN) U17.6(VCC)
VCC_1V8: C12.1 R22.1 R29.1 R31.1 R33.1 R35.1 R79.1 R80.1 R94.2 U3.68(VCC_1V8) U4.12(VCCA)
VCC_3V3: C1.1 C5.1 C6.1 C7.1 C8.1 C9.1 C13.1 C14.1 C19.1 C27.1 C33.1 C34.1 C35.1 C36.1 J4.2(VBAT1) J4.24(VBAT5) J4.39(VBAT2) J4.41(VBAT3) J4.52(VBAT4) J12.1 J12.17 L1.2 Q2.2(SOURCE) R1.1 R9.1 R10.1 R15.1 R26.1 R27.1 R28.1 R30.1 R32.1 R34.1 R36.1 R45.1 R51.1 R64.1 R65.1 R74.1 R75.1 U1.9(VCC) U4.11(VCCB) U5.21(VCC) U16.5(IN)
VCC_3V3_EN: R14.1 U3.70(VCC_3V3)
VCC_WLAN: C28.1 C29.1 Q2.3(DRAIN) U10.6(VDD_3V3)
VDD_CAM0_5V: C37.1 C38.1 J5.1 J5.2 J5.3 U13.1(OUT)
VDD_CAM1_5V: C39.1 C40.1 J6.1 J6.2 J6.3 U14.1(OUT)
VDD_LCD_3V3: C43.1 C44.1 J7.37 J7.38 R63.1 U16.1(OUT)
VDD_LCD_5V: C41.1 C42.1 J7.39 J7.40 U15.1(OUT)
CAM0_nRST: J5.22 U5.2(P0_1)
CAM0_PWDN: J5.15 U5.1(P0_0)
CAM0_PWR_EN: R59.1 U3.59(MIPI_CLK0_OUT___VI_CIF_CLKO_M0___GPIO3_C4_d)
CAM1_nRST: J6.22 U5.4(P0_3)
CAM1_PWDN: J6.15 U5.3(P0_2)
CAM1_PWR_EN: R61.1 U3.58(VI_BT656_D2_M0___VI_BT1120_D10___PWM7_IR_M2___MIPI_CLK1_OUT___VI_CIF_D10___GPIO3_C6_d)
DBG_DN: R3.2 U1.7(D1-)
DBG_DP: R2.2 U1.1(D1+)
DBG_RX: J13.2 R89.1 Z2.1
DBG_TX: J13.3 R88.1 Z1.1
DC_EN: R12.2 R14.2 U2.1(EN)
DISP: J7.7 R63.2
DM1: J3.2(D-) R37.1 U9.2(D1-) U9.9(NC2)
DM2: J3.8(D-) R40.1 U9.5(D2-) U9.6(NC4)
DP1: J3.3(D+) R38.1 U9.1(D1+) U9.10(NC1)
DP2: J3.9(D+) R42.1 U9.4(D2+) U9.7(NC3)
FEPHY_LINK: R78.1 U3.102(VI_BT656_D7_M0___VI_BT1120_D15___PWM1_M2___VI_CIF_D15___GPIO3_D3_d)
FEPHY_RXN: R70.1 U3.25(FEPHY_RXN)
FEPHY_RXP: R71.1 U3.26(FEPHY_RXP)
FEPHY_SPD: R76.1 U3.103(VI_CIF_VSYNC_M0___GPIO3_C5_d)
FEPHY_TXN: R72.1 U3.28(FEPHY_TXN)
FEPHY_TXP: R73.1 U3.29(FEPHY_TXP)
GPIO0_A0: J12.7 U3.111(RTC_CLK_OUT___CLK_32K_IN___REF_CLK_OUT___UART0_RX_M0___GPIO0_A0_z)
GPIO0_A1: J12.11 U3.112(PWM2_M0___UART0_TX_M0___GPIO0_A1_d)
GPIO0_A2: J12.13 U3.113(PWM3_IR_M0___GPIO0_A2_d)
GPIO0_A4: J12.15 U3.115(PWM1_M0___PWR_CTRL_M0___GPIO0_A4_d)
GPIO0_A5: J12.16 U3.116(I2C1_SCL_M0___PWM5_M0___UART1_RTS_M0___GPIO0_A5_d)
GPIO5_P1_0: J12.18 U5.10(P1_0)
GPIO5_P1_1: J12.22 U5.11(P1_1)
GPIO5_P1_2: J12.26 U5.12(P1_2)
HUB_3V3: C20.1 C21.1 R39.1 R41.1 R43.1 R45.2 U6.1(OVCUR#) U6.20(VDD3V3)
I2C3_SCL_LT: J6.6 J12.5 R23.1 R34.2 U4.8(B3)
I2C3_SCL_M2: R33.2 U3.75(VI_BT656_D5_M0___VI_BT1120_D13___UART5_RTS_M2___I2C3_SCL_M2___VI_CIF_D13___GPIO3_D1_d) U4.3(A3)
I2C3_SDA_LT: J6.5 J12.3 R24.1 R36.2 U4.7(B4)
I2C3_SDA_M2: R35.2 U3.76(VI_BT656_D6_M0___VI_BT1120_D14___UART5_CTS_M2___I2C3_SDA_M2___VI_CIF_D14___GPIO3_D2_d) U4.4(A4)
I2C4_SCL_LT: J5.6 J7.1 J12.28 R30.2 U4.10(B1)
I2C4_SCL_M2: R29.2 U3.72(VI_BT656_D3_M0___VI_BT1120_D11___UART5_TX_M2___I2C4_SCL_M2___VI_CIF_D11___GPIO3_C7_d) U4.1(A1)
I2C4_SDA_LT: J5.5 J7.2 J12.27 R32.2 U4.9(B2)
I2C4_SDA_M2: R31.2 U3.73(VI_BT656_D4_M0___VI_BT1120_D12___UART5_RX_M2___I2C4_SDA_M2___VI_CIF_D12___GPIO3_D0_d) U4.2(A2)
LCD_INT: J7.3 R65.2 U3.6(I2C0_SDA_M0___UART1_RX_M0___GPIO1_A4_d)
LCD_PWM_BL: J7.6 U3.4(VI_CIF_D0_M1___CPU_AVS___PWM0_M0___GPIO1_A2_d)
LCD_RST: J7.4 R64.2 U3.5(I2C0_SCL_M0___UART1_TX_M0___GPIO1_A3_d)
LINEOUT: C54.1 U3.89(CODEC_LINEOUT)
MICIN0_N: C50.2 J9.2 R83.1 U3.96(MICIN0_N)
MICIN0_P: C50.1 J9.1 R81.1 U3.97(MICIN0_P)
MICIN1_N: C51.2 J10.2 R84.1 U3.99(MICIN1_N)
MICIN1_P: C51.1 J10.1 R82.1 U3.100(MICIN1_P)
MIPI_CSI_RX_CLK0N: J5.10 U3.49(VI_BT656_D0_M0___VI_BT1120_D8___LVDS_RX_CLK0N___MIPI_CSI_RX_CLK0N___VI_CIF_D8_M0___GPI3_C0_d)
MIPI_CSI_RX_CLK0P: J5.9 U3.50(VI_BT656_D1_M0___VI_BT1120_D9___LVDS_RX_CLK0P___MIPI_CSI_RX_CLK0P___VI_CIF_D9_M0___GPI3_C1_d)
MIPI_CSI_RX_CLK1N: J6.10 U3.40(VI_BT1120_D2___LVDS_RX_CLK1N___MIPI_CSI_RX_CLK1N___VI_CIF_D2_M0___GPI3_B2_d)
MIPI_CSI_RX_CLK1P: J6.9 U3.41(VI_BT1120_D3___LVDS_RX_CLK1P___MIPI_CSI_RX_CLK1P___VI_CIF_D3_M0___GPI3_B3_d)
MIPI_CSI_RX_D0N: J5.12 U3.55(VI_BT656_CLK_M0___VI_BT1120_CLK___LVDS_RX_D0N___MIPI_CSI_RX_D0N___VI_CIF_CLKI_M0___GPI3_C2_d)
MIPI_CSI_RX_D0P: J5.11 U3.56(LVDS_RX_D0P___MIPI_CSI_RX_D0P___VI_CIF_HREF_M0___GPI3_C3_d)
MIPI_CSI_RX_D1N: J5.8 U3.52(VI_BT1120_D6___LVDS_RX_D1N___MIPI_CSI_RX_D1N___VI_CIF_D6_M0___GPI3_B6_d)
MIPI_CSI_RX_D1P: J5.7 U3.53(VI_BT1120_D7___LVDS_RX_D1P___MIPI_CSI_RX_D1P___VI_CIF_D7_M0___GPI3_B7_d)
MIPI_CSI_RX_D2N: J6.12 U3.46(VI_BT1120_D4___LVDS_RX_D2N___MIPI_CSI_RX_D2N___VI_CIF_D4_M0___GPI3_B4_d)
MIPI_CSI_RX_D2P: J6.11 U3.47(VI_BT1120_D5___LVDS_RX_D2P___MIPI_CSI_RX_D2P___VI_CIF_D5_M0___GPI3_B5_d)
MIPI_CSI_RX_D3N: J6.8 U3.43(VI_BT1120_D0___LVDS_RX_D3N___MIPI_CSI_RX_D3N___VI_CIF_D0_M0___GPI3_B0_d)
MIPI_CSI_RX_D3P: J6.7 U3.44(VI_BT1120_D1___LVDS_RX_D3P___MIPI_CSI_RX_D3P___VI_CIF_D1_M0___GPI3_B1_d)
NPOR: R87.1 U3.119(NPOR)
PWM3_IR_M1: J12.29 U3.7(PWM3_IR_M1___UART4_RX_M0___GPIO1_B0_d)
PWM7_IR_M1: J12.12 U3.8(SPI1_CS1_M0___VI_CIF_D1_M1___PWM7_IR_M1___UART4_TX_M0___GPIO1_B1_d)
RGB_LCD_EN: R67.1 U3.117(I2C1_SDA_M0___PWM6_M0___UART1_CTS_M0___GPIO0_A6_d)
S_SET: R1.2 SW1.1(A1) U1.10(S)
SARADC_IN0_REC: R90.1 U3.87(SARADC_IN0___GPIO4_C0_z)
SARADC_IN1: R91.1 U3.86(PWM1_M1___SARADC_IN1___GPIO4_C1_z)
SDMMC_CLK: D7.1 J2.5(CLK) U3.78(JTAG_LPMCU_TCK_M1____I2C0_SCL_M2___PWM10_M0___UART5_RTS_M0___SDMMC_CLK___GPIO3_A4_d)
SDMMC_CMD: R18.1 U3.84(JTAG_LPMCU_TMS_M1___I2C0_SDA_M2___PWM11_IR_M0___UART5_CTS_M0___SDMMC_CMD___GPIO3_A5_u)
SDMMC_D0: R19.1 U3.80(PWM8_M0___UART2_RX_M0___SDMMC_D0___GPIO3_A3_u)
SDMMC_D1: R20.1 U3.81(PWM9_M0___UART2_TX_M0___SDMMC_D1___GPIO3_A2_u)
SDMMC_D2: R16.1 U3.82(JTAG_HPMCU_TCK_M1___JTAG_CPU_TCK_M0___UART5_RX_M0___SDMMC_D2___GPIO3_A7_u)
SDMMC_D3: R17.1 U3.83(JTAG_HPMCU_TMS_M1___JTAG_CPU_TMS_M0___UART5_TX_M0___SDMMC_D3___GPIO3_A6_u)
SDMMC_DET: R21.1 U3.79(SDMMC_DET___GPIO3_A1_u)
SIM_CLK0: J4.12(USIM-CLK) R54.1
SIM_DATA0: J4.10(USIM-DATA) R56.1
SIM_RST0: J4.14(USIM-RST) R55.1
SIM_VDD: J4.8(USIM-VDD) J14.1(VCC) R53.1 U12.1
SPI1_CLK_M0: J12.23 U3.108(SPI1_CLK_M0___I2C2_SCL_M1___UART1_RX_M2___EMMC_D5___GPIO4_A7_u)
SPI1_CS0_M0: J12.24 U3.109(SPI1_CS0_M0___I2C2_SDA_M1___UART1_TX_M2___EMMC_D4___GPIO4_A5_u)
SPI1_MISO_M0: J12.21 U3.106(SPI1_MISO_M0___I2C0_SDA_M1___UART0_RX_M2___EMMC_D7___GPIO4_A0_u)
SPI1_MOSI_M0: J12.19 U3.107(SPI1_MOSI_M0___I2C0_SCL_M1___UART0_TX_M2___EMMC_D6___GPIO4_A1_u)
SPK_CTRL: U5.8(P0_7) U17.1(SDN)
SYS_LED: R11.1 U5.5(P0_4)
UART2_DBG_RX: R89.2 U3.9(JTAG_HPMCU_TMS_M0___JTAG_LPMCU_TMS_M0___JTAG_CPU_TMS_M1___UART2_RX_M1___GPIO1_B3_u)
UART2_DBG_TX: R88.2 U3.10(JTAG_HPMCU_TCK_M0___JTAG_LPMCU_TCK_M0___JTAG_CPU_TCK_M1___UART2_TX_M1___GPIO1_B2_d)
UART3_RX_M0: J12.10 U3.3(I2C2_SDA_M0___PWM4_M0___UART3_RX_M0___GPIO1_A1_d)
UART3_TX_M0: J12.8 U3.2(I2C2_SCL_M0___PWM7_IR_M0___UART3_TX_M0___GPIO1_A0_d)
USB_4G_DM3: R57.2 U6.7(DM3)
USB_4G_DP3: R58.2 U6.8(DP3)
USB_DM1: R37.2 U6.11(DM1)
USB_DM2: R40.2 U6.9(DM2)
USB_DP1: R38.2 U6.12(DP1)
USB_DP2: R42.2 U6.10(DP2)
USB_HOST_EN: R47.1 U5.7(P0_6) U7.4(EN) U8.4(EN)
USB_HUB_DM: U1.6(D2-) U6.14(DMU)
USB_HUB_DP: U1.2(D2+) U6.15(DPU)
USB_RV_DM: U1.5(D-) U3.93(USB_DM)
USB_RV_DP: U1.3(D+) U3.94(USB_DP)
USB_VBUS0: C17.1 C18.1 J3.1(VBUS) U7.1(OUT)
USB_VBUS1: C22.1 C23.1 J3.7(VBUS) U8.1(OUT)
USB_VBUSDET: R6.2 R7.1 U3.91(USB_VBUSDET)
USB_WLAN_DM4: R49.1 U6.5(DM4)
USB_WLAN_DP4: R50.1 U6.6(DP4)
VO_LCDC_CLK: R95.1 U3.12(I2C3_SCL_M1___AUD_DSM_N___UART5_TX_M1___PWM11_IR_M2___VI_CIF_CLKO_M1___VO_LCDC_CLK___GPIO1_D3_d)
VO_LCDC_D0: J7.17 U3.16(VI_BT656_D7_M1___UART4_CTS_M1___PWM11_IR_M1_________VI_CIF_D9_M1___VO_LCDC_D0___GPIO1_C7_d)
VO_LCDC_D1: J7.16 U3.17(VI_BT656_D6_M1___UART4_RTS_M1___PWM10_M1___VI_CIF_D8_M1___VO_LCDC_D1___GPIO1_C6_d)
VO_LCDC_D2: J7.15 U3.18(VI_BT656_D5_M1___SDIO_D2_M1___UART4_TX_M1___PWM9_M1___VI_CIF_D7_M1___VO_LCDC_D2___GPIO1_C5_d)
VO_LCDC_D3: J7.14 U3.19(VI_BT656_D4_M1____SDIO_D3_M1___UART4_RX_M1___PWM8_M1___VI_CIF_D6_M1___VO_LCDC_D3___GPIO1_C4_d)
VO_LCDC_D4: J7.13 U3.20(VI_BT656_D3_M1___I2C4_SDA_M1___SDIO_CMD_M1___SPI0_MISO_M0___PWM6_M2___VI_CIF_D5_M1___VO_LCDC_D4___GPIO1_C3_d)
VO_LCDC_D5: J7.12 U3.21(VI_BT656_D2_M1___I2C4_SCL_M1___SDIO_CLK_M1___SPI0_MOSI_M0___PWM5_M2___VI_CIF_D4_M1___VO_LCDC_D5___GPIO1_C2_d)
VO_LCDC_D6: J7.25 U3.22(VI_BT656_D1_M1___SDIO_D0_M1___SPI0_CLK_M0___PWM4_M2___VI_CIF_D3_M1___VO_LCDC_D6___GPIO1_C1_d)
VO_LCDC_D7: J7.24 U3.23(VI_BT656_D0_M1___SDIO_D1_M1___SPI0_CS0_M0___PWM2_M2___VI_CIF_D2_M1___VO_LCDC_D7___GPIO1_C0_d)
VO_LCDC_D8: J7.23 U3.105(I2C4_SDA_M0___UART1_CTS_M1___VO_LCDC_D8___I2S0_SCLK___SDIO_D1_M0___GPIO2_A0_d)
VO_LCDC_D9: J7.22 U3.104(I2C4_SCL_M0___UART1_RTS_M1___VO_LCDC_D9___I2S0_LRCK___SDIO_D0_M0___GPIO2_A1_d)
VO_LCDC_D10: J7.21 U3.38(VO_LCDC_D10___I2S0_MCLK___SDIO_CLK_M0___GPIO2_A2_d)
VO_LCDC_D11: J7.20 U3.37(VO_LCDC_D11___I2S0_SDO3_SDI1___SDIO_CMD_M0___GPIO2_A3_d)
VO_LCDC_D12: J7.33 U3.36(UART1_TX_M1___VO_LCDC_D12___I2S0_SDO0___SDIO_D3_M0___GPIO2_A4_d)
VO_LCDC_D13: J7.32 U3.35(UART1_RX_M1___VO_LCDC_D13___I2S0_SDI0____SDIO_D2_M0___GPIO2_A5_d)
VO_LCDC_D14: J7.31 U3.34(FLASH_TRIGOUT___I2C3_SCL_M0___PWM2_M1___VO_LCDC_D14___I2S0_SDO2_SDI2___UART0_RTS_M1___GPIO2_A6_d)
VO_LCDC_D15: J7.30 U3.33(PRELIGHT_TRIGOUT___I2C3_SDA_M0___PWM4_M1___VO_LCDC_D15___I2S0_SDO1_SDI3___UART0_CTS_M1___GPIO2_A7_d)
VO_LCDC_D16: J7.29 U3.31(PWM5_M1___VO_LCDC_D16___I2C1_SCL_M1___UART0_RX_M1___GPIO2_B0_d)
VO_LCDC_D17: J7.28 U3.32(PWM6_M1___VO_LCDC_D17___I2C1_SDA_M1___UART0_TX_M1___GPIO2_B1_d)
VO_LCDC_DEN: J7.8 U3.15(VI_BT656_CLK_M1___UART3_TX_M1___UART5_RTS_M1___PWM3_IR_M2___VI_CIF_CLKI_M1___VO_LCDC_DEN___GPIO1_D0_d)
VO_LCDC_HSYNC: R96.1 U3.14(UART3_RX_M1___UART5_CTS_M1___PWM10_M2___VI_CIF_HREF_M1___VO_LCDC_HSYNC___GPIO1_D1_d)
VO_LCDC_VSYNC: R97.1 U3.13(SPI0_CS1_M0___I2C3_SDA_M1___AUD_DSM_P___UART5_RX_M1___PWM0_M1___VI_CIF_VSYNC_M1___VO_LCDC_VSYNC___GPIO1_D2_d)
WIFI_PWR_EN: R52.1 U5.6(P0_5)
XL9535_INT: R25.1 U3.114(PWR_CTRL_M1___GPIO0_A3_u)
N19537137: J11.1 U17.8(VO2)
N19537140: J11.2 R86.2 U17.5(VO1)
N19537426: R85.2 R86.1 U17.4(IN-)
N19538834: C55.1 U17.2(BYPASS) U17.3(IN+)
N21425973: J1.A5(CC1) R5.1
N21425975: J1.B5(CC2) R4.1
N21432968: D1.2 J1.A6(DP1) J1.B6(DP2) R2.1
N21432971: D2.2 J1.A7(DN1) J1.B7(DN2) R3.1
N23042290: LED2.2(ANODE) R9.2
N23042305: LED2.1(CATHODE) Q1.3(COLLECTOR)
N23503644: D10.1 J2.1(DAT2) R16.2
N23503648: D9.1 J2.2(CD/DAT3) R17.2
N23503652: D8.1 J2.3(CMD) R18.2
N23503668: D6.1 J2.7(DAT0) R19.2
N23503672: D5.1 J2.8(DAT1) R20.2
N23503676: D4.1 J2.9(CD) R21.2
N23656755: L1.1 U2.3(SW)
N23656759: C5.2 R10.2 R13.1 U2.5(FB)
N23695731: C15.1 U6.3(XOUT) Y1.3
N23695751: C16.2 U6.4(XIN) Y1.1
N23695813: R43.2 U6.18(PSELF)
N23695825: R41.2 U6.16(RESET#/CDP)
N23695839: R39.2 U6.17(NC2)
N23695875: R44.1 U6.13(LED3/SCL)
N23697039: R48.1 U8.3(ISET)
N23697128: R46.1 U7.3(ISET)
N23704623: R67.2 R68.1 U15.4(EN) U16.4(EN)
N23704651: R69.1 U16.3(ISET)
N23704740: R66.1 U15.3(ISET)
N23717309: C47.1 J8.13(SH1) J8.14(SH2) R77.1
N23717611: C46.1 J8.4(CT2)
N23717616: C45.1 J8.5(CT1)
N23717674: J8.1(TD+) R73.2
N23717677: J8.2(TD-) R72.2
N23717680: J8.3(RD+) R71.2
N23717683: J8.6(RD-) R70.2
N23718997: C24.2 C26.1 U10.2(RF_OUT)
N23719030: C27.2 Q2.1(GATE) R51.2 R52.2
N23719056: R50.2 U10.4(DP)
N23719058: R49.2 U10.5(DM)
N23719088: C24.1 C25.1 CN1.1
N23722440: C48.1 R79.2 R81.2
N23723488: C49.1 R80.2 R82.2
N23729410: Q3.1(BASE) R76.2
N23729602: Q4.1(BASE) R78.2
N23729707: J8.9(LED_G_A) R75.2
N23729710: J8.10(LED_G_K) Q4.3(COLLECTOR)
N23729715: J8.11(LED_Y_K) Q3.3(COLLECTOR)
N23729724: J8.12(LED_Y_A) R74.2
N23759751: Q1.1(BASE) R11.2
N23760169: LED1.2(ANODE) R8.2
N23768401: R59.2 R93.1 U13.4(EN)
N23768412: R60.1 U13.3(ISET)
N23768535: R61.2 R92.1 U14.4(EN)
N23768546: R62.1 U14.3(ISET)
N23809669: C30.1 J14.7(I/O) R53.2 R56.2 U12.5
N23809673: C32.1 J14.2(RST) R55.2 U12.6
N23809721: C31.1 J14.3(CLK) R54.2 U12.4
N23809831: J4.38(USB-D+) R58.1
N23809847: J4.36(USB-D-) R57.1
N23819356: D11.2 R87.2 SW2.3(B1) SW2.4(B2)
N23820735: C54.2 R85.1
N23825175: R28.2 U5.24(A2)
N23825177: R27.2 U5.23(A1)
N23825179: R26.2 U5.18(A0)
N23825209: R23.2 U5.19(SCL)
N23825224: R24.2 U5.20(SDA)
N23825226: R25.2 U5.22(\~{INT})
N23825314: R22.2 U4.6(OE)
N23848065: D12.2 R90.2 SW3.3(B1) SW3.4(B2)
N23848217: D13.2 R91.2 R94.1 SW4.3(B1) SW4.4(B2)
N23865153: J7.9 R97.2
N23865156: J7.10 R96.2
N23865159: J7.11 R95.2

Not connected (* = marked no-connect by the designer): J1 A8(SBU1)* B8(SBU2)*; J4 1(MIC-P)* 3(MIC-N)* 5(SPK-P)* 6(NC1)* 7(SPK-N)* 11(VDD-EXT)* 13(RESERVED)* 16(RESERVED6)* 17(RESERVED5)* 19(WAKEUP-IN)* 20(W-DISABLE)* 22(PERST1)* 23(UART-RXD)* 25(UART-RTS)* 28(UART-CTS)* 30(UART-DCD)* 31(UART-TXD)* 32(WAKEUP-OUT)* 33(PERST2)* 42(LED-WWAN)* 44(USIM-PRESENCE)* 45(RESERVED1)* 46(UART-DTR)* 47(RESERVED2)* 48(NC2)* 49(RESERVED3)* 51(RESERVED4)*; J5 13* 14* 16* 17* 19* 20*; J6 13* 14* 16* 17* 19* 20*; J8 7(NC)*; J14 4(CD)* 6(VPP)*; SS1 1(NC)*; SS2 1(NC)*; SS3 1(NC)*; SS4 1(NC)*; U5 13(P1_3)* 14(P1_4)* 15(P1_5)* 16(P1_6)* 17(P1_7)*; U6 2(NC1)* 19(VDD5)* 21(LED4/SDA)* 22(LED1)* 23(LED2)* 24(PWREN#)*; U12 3*

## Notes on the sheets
sheet 1
- 野火_LubanCat_RV06_IOS_底板原理图
- Page 1
- Content
- Page 24
- Page 2
- Historic Version
- Page 25
- Page 3
- POWER DIAGRAM
- Page 26
- Page 4
- TYPE_C/Switch
- Page 27
- Page 5
- EVM Connector
- Page 28
- Page 6
- TF CARD/IO Expand
- Page 29
- Page 7
- USB HUB
- Page 30
- Page 8
- USB_WLAN/4G_MOUDEL
- Page 31
- Page 9
- MIPI CSI/RGB Display
- Page 32
- Page 10
- ETH
- Page 33
- Page 11
- MIC/SPK
- Page 34
- Page 12
- DEBUG/PIN OUT/KEY
- Page 35
- Page 13
- Page 36
- Page 14
- Page 37
- Page 15
- Page 38
- Page 16
- Page 39
- Page 17
- Page 40
- Page 18
- Page 41
- Page 19
- Page 20
- Page 21
- Page 22
- Page 23
sheet 2
- Historic Version
- 版本号
- 日期
- 设计
- 描述
- V0R1
- 2024-06-10
- ghs
- 初始版本
- V0R2
- 2024-11-14
- ghs
- 修正SYS灯限流电阻，增加U13，U14的下拉电阻，删除MIC多余的电路
- 增加SRADC_IN1的上拉电阻
sheet 3
- POWER DIAGRAM
- RK1106G Core
- MAX 1A
- Singal Switcher
- USB HUB
- TF CARD
- WLAN Module
- DC-DC
- VCC_3V3
- I/O Expand
- 4G Module
- 3.3V  3A
- Level Translation
- PIN OUT
- USB_VBUS0
- TYPE C IN
- SWitch
- USB_VBUS1
- USB20 PORT
- VCC5V0_SYS
- GPIO  EN
- OCP 2A
- USB Type-C 3A
- SWitch
- VDD_CAM0_5V
- VDD_CAM1_5V
- MIPI CSI RX0
- MAX 1A
- MIPI CSI RX1
- SWitch
- VDD_LCD_5V
- MAX 1A
- RGB DISPLAY
- VCC_3V3
- SWitch
- MAX 1A
- VDD_LCD_3V3
- SPK PA
- PIN OUT VCC
- Bot Power in
- RV1106G Core Power out
- VCC_1V8
- Level Translation
- VCC_1V8 MAX 0.2A
- MIC power
- Bot Power in
- RV1106G Core Power out
- VCC_3V3 MAX 2A
sheet 4
- SOM Connector
sheet 5
- HUB Chip
- USB2.0 PORT
- 2A限流
- GPIO5_P0_6
- ESD
- 2A限流
sheet 6
- 100M ETH
- GPIO3_C5
- GPIO3_D3
sheet 7
- MIC
- SPK PA
- GPIO5_P0_7
sheet 8
- TYPE C IN
- Singal Switcher
- 5V 3A
- Pull S_SET low to connect RV1106G
- 3.23529V
- VCC5V0_SYS --> VCC_3V3
- PWR/SYS_LED
- RED
- FB 0.6V
- GREEN
- GPIO5_P0_4
sheet 9
- PIN OUT
- UART5_CTS_M2
- I2C3_SDA_M2
- GPIO3_D2
- REF_CLK_OUT
- UART5_RTS_M2
- I2C3_SCL_M2
- UART0_RX_M0
- GPIO0_A0
- GPIO3_D1
- GPIO1_A0
- I2C2_SCL_M0
- PWM7_IR_M0
- UART3_TX_M0
- GPIO1_A1
- I2C2_SDA_M0
- PWM4_M0
- UART3_RX_M0
- PWM2_M0
- UART0_TX_M0
- GPIO0_A1
- GPIO1_B1
- UART4_TX_M0
- PWM7_IR_M1
- PWM3_IR_M0
- GPIO0_A2
- PWM1_M0
- GPIO0_A4
- GPIO0_A5
- PWM5_M0
- SPI1_MOSI_M0
- I2C0_SCL_M1
- UART0_TX_M2
- GPIO4_A1
- SPI1_MISO_M0
- I2C0_SDA_M1
- UART0_RX_M2
- GPIO4_A0
- SPI1_CLK_M0
- I2C2_SCL_M1
- UART1_RX_M2
- GPIO4_A7
- GPIO4_A5
- UART1_TX_M2
- I2C2_SDA_M1
- SPI1_CS0_M0
- UART5_RX_M2
- I2C4_SDA_M2
- GPIO3_D0
- GPIO3_C7
- UART5_TX_M2
- I2C4_SCL_M2
- PWM3_IR_M1
- UART4_RX_M0
- GPIO1_B0
- Only Support 3.3V
- KEY
- DEBUG
- I/O: 3.3V
- KLXES15AAA1*2
sheet 10
- TF CARD
- I2C Level Translation
- I/O Expand GPIO5
- GPIO0_A3
- I2C Addr:0x21
sheet 11
- USB_WLAN
- Z0=50Ω
- Z0=50Ω
- GPIO5_P0_5
- 4G MOUDEL
sheet 12
- CAM0 POWER
- CAM RX0
- CAM RX1
- GPIO3_C4
- GPIO5_P0_0
- GPIO5_P0_2
- GPIO5_P0_1
- GPIO5_P0_3
- CAM1 POWER
- RGB DISPLAY
- GPIO3_C6
- LCD POWER
- GPIO0_A6
- PWM0_M0
- GPIO1_A3
- GPIO1_A4
